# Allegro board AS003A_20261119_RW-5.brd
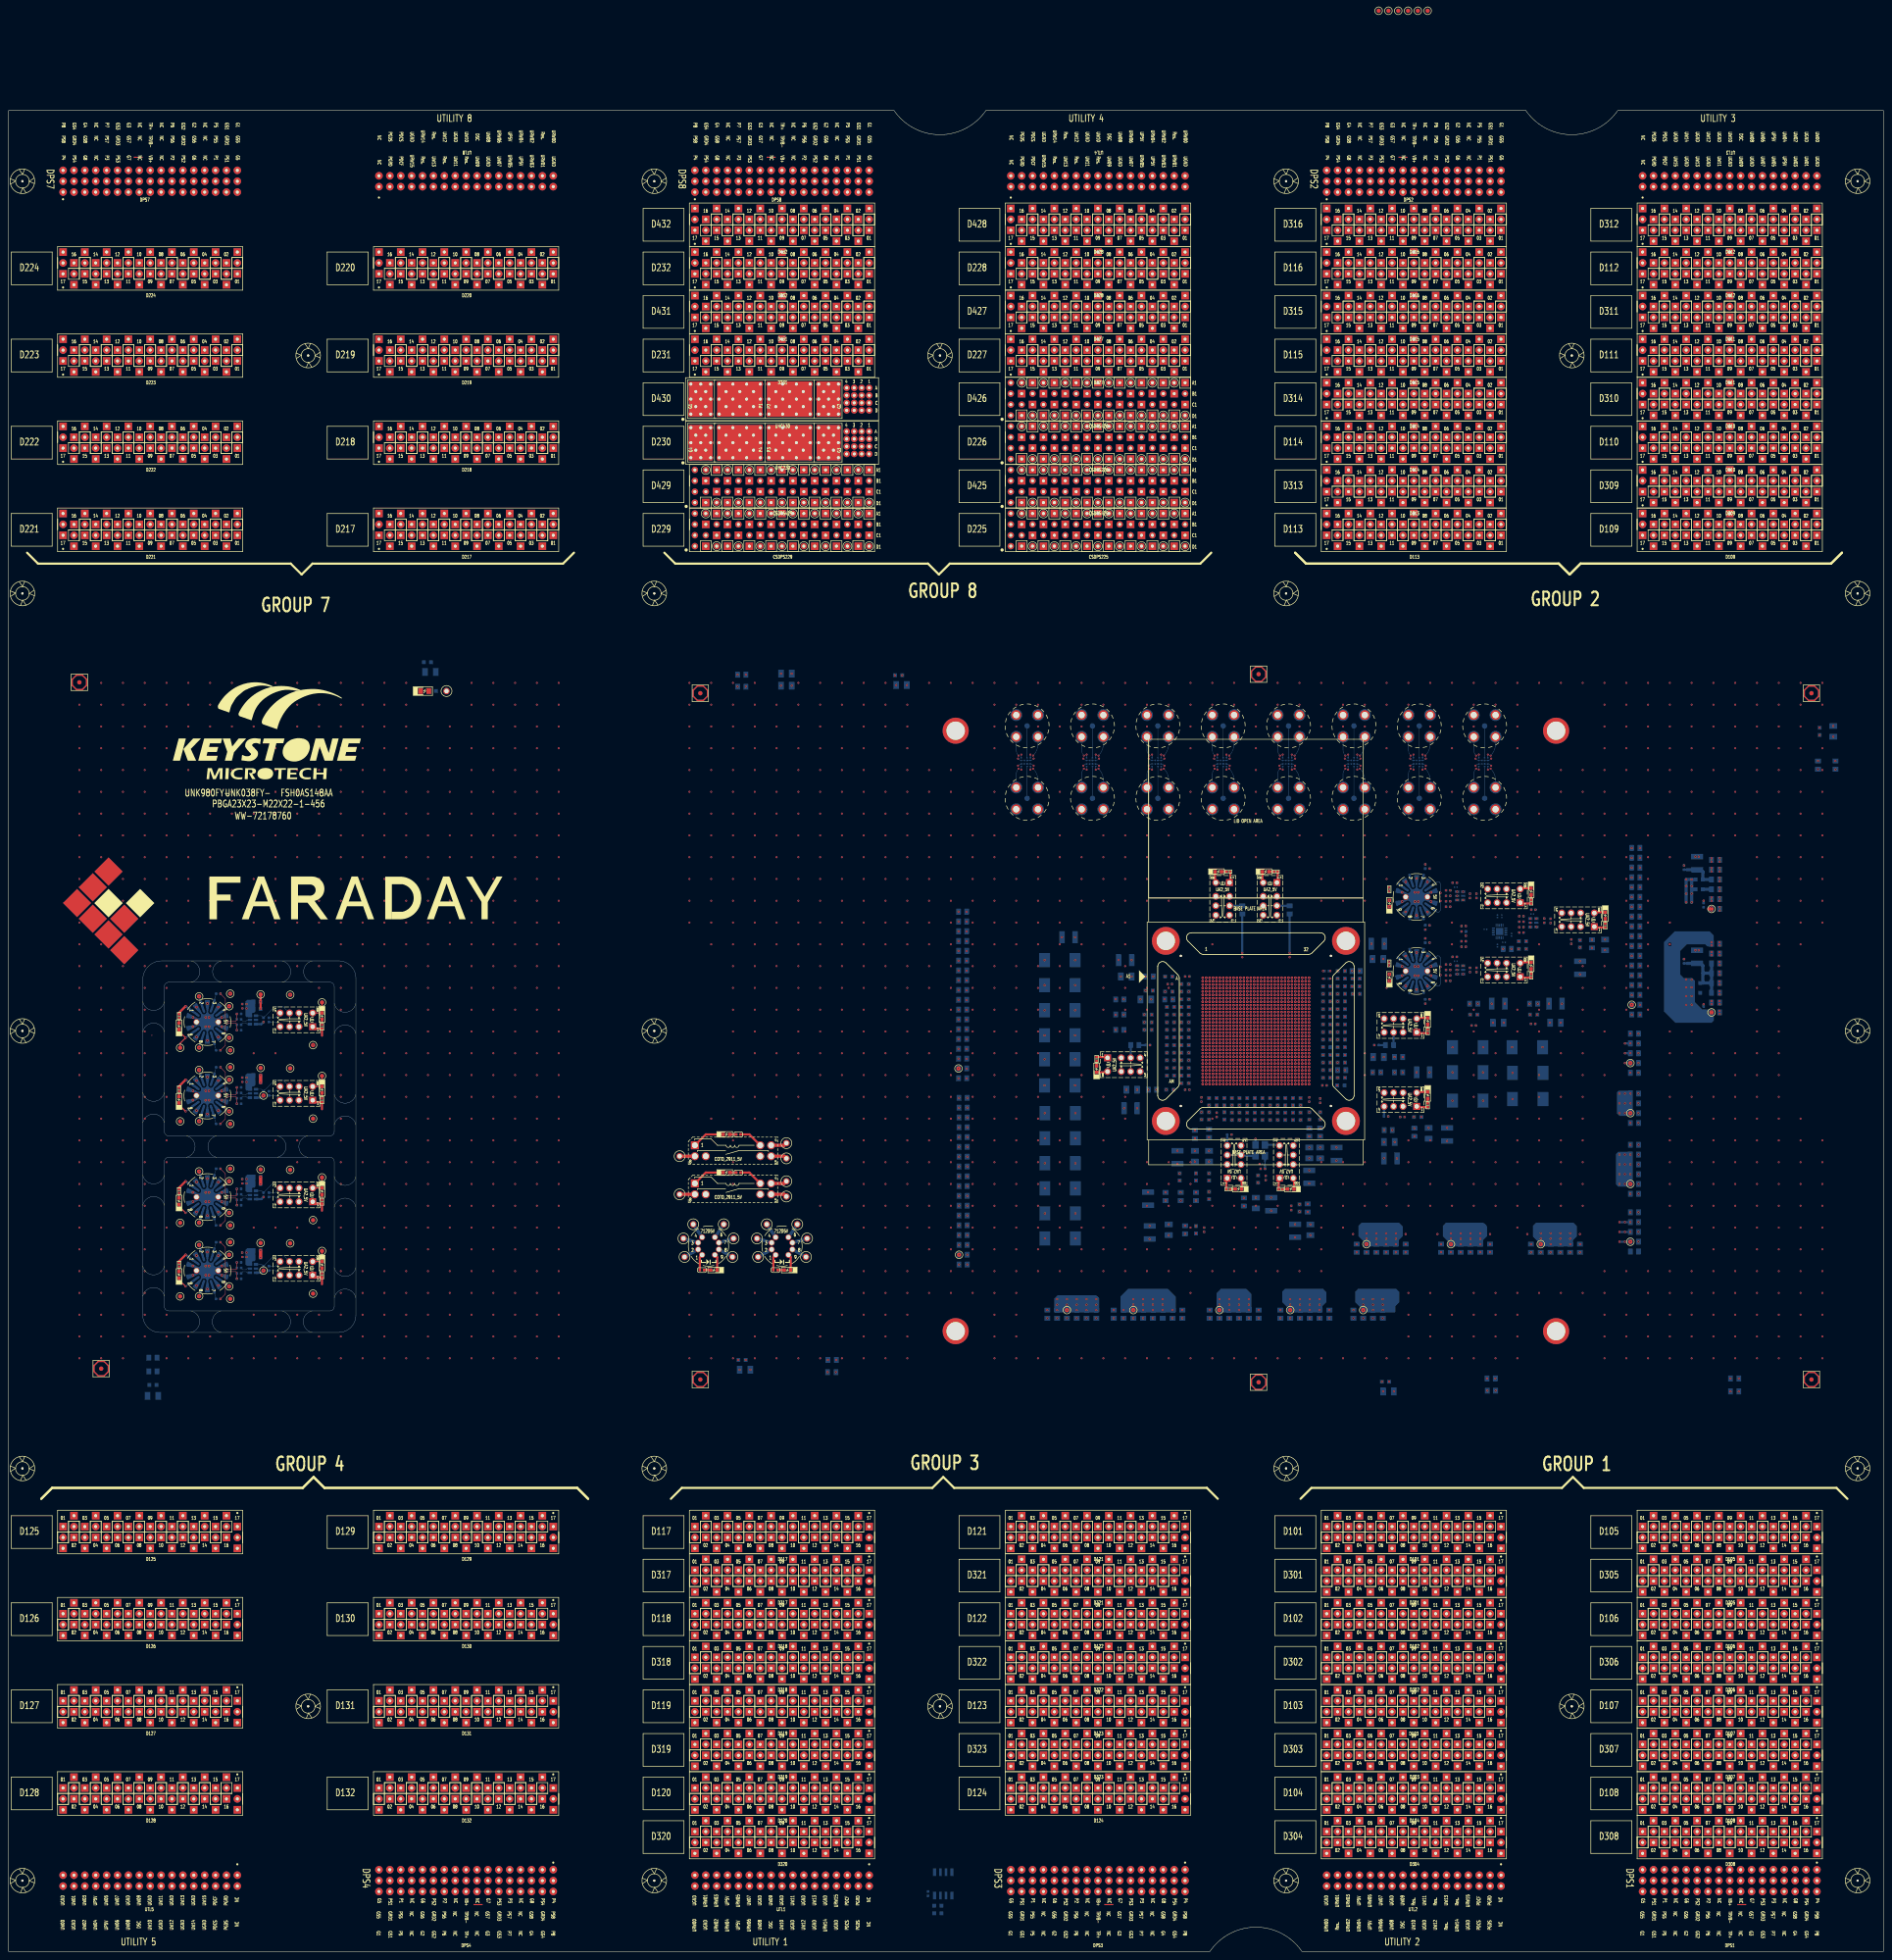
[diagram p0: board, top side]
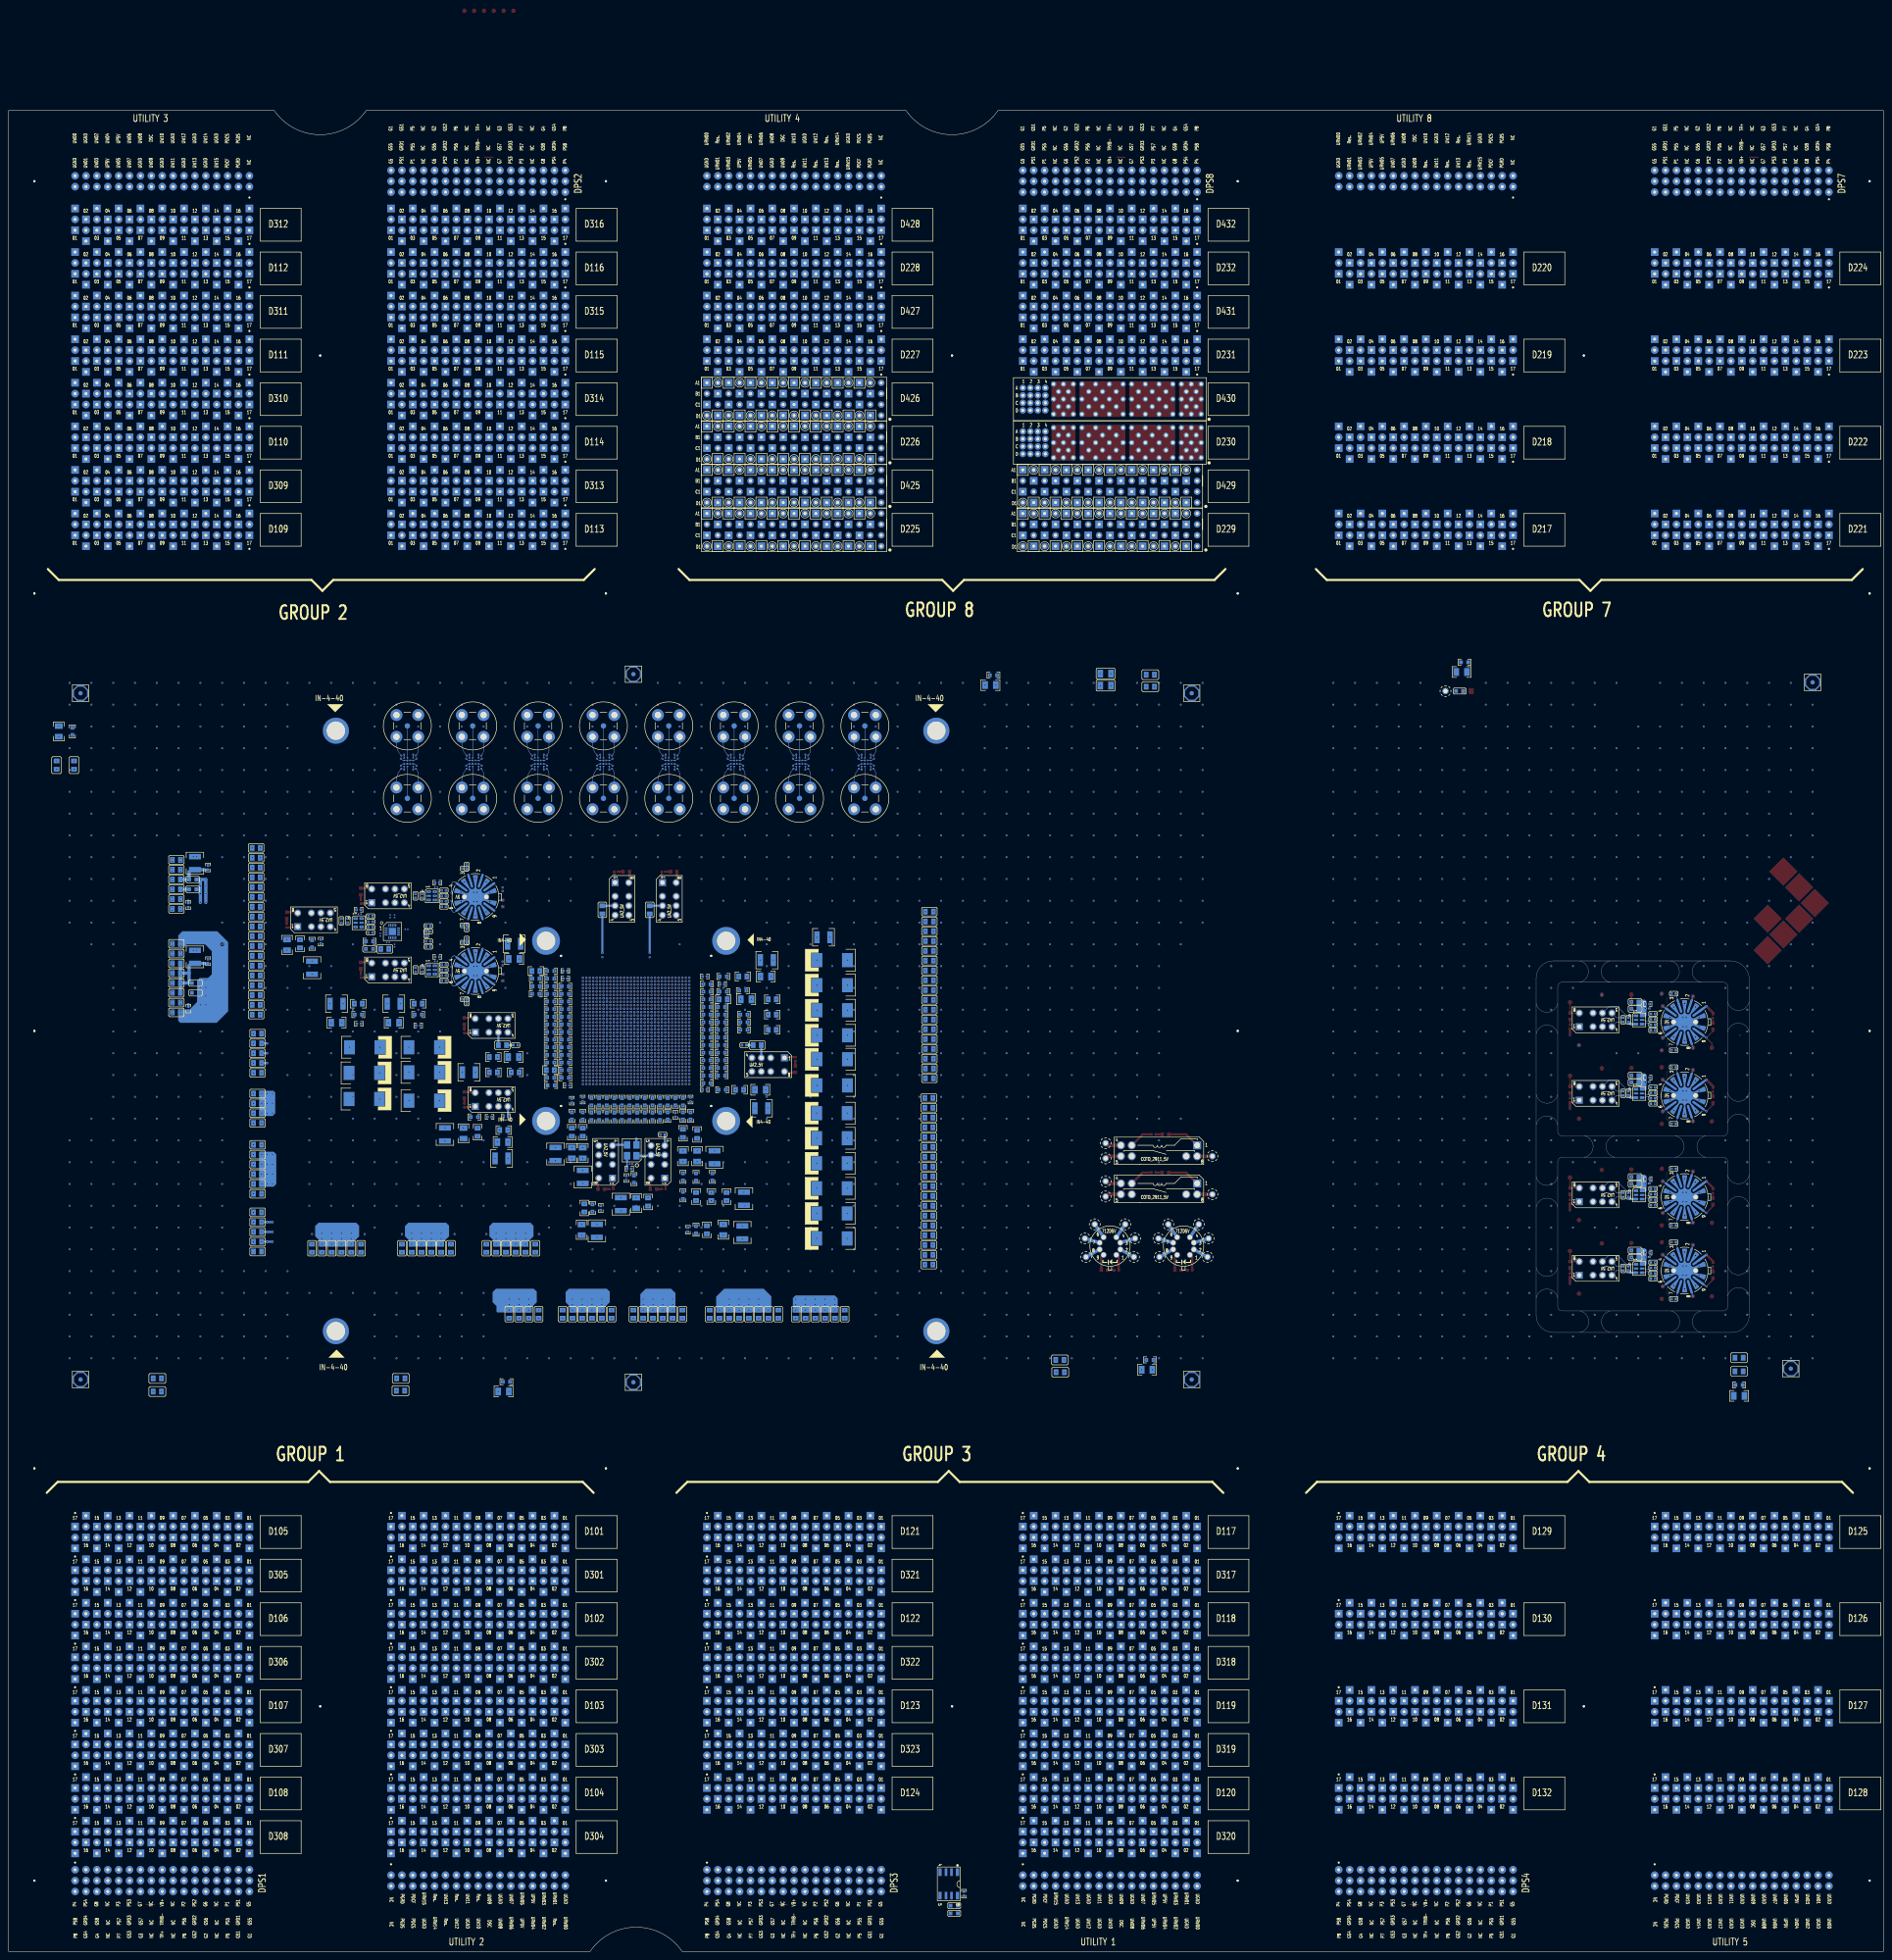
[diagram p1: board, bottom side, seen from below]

Outline 437.15 x 429.26 mm; copper layers: TOP, L02_DGND, L03_DIG, L04_DGND, L05_DIG, L06_DGND, L07_DIG, L08_DGND, L09_DIG, L10_DGND, L11_POWER, L12_POWER, L13_DGND, L14_POWER, L15_POWER, L16_DGND, L17_CBIT, L18_5V, L19_DGND, L20_POWER, L21_DGND, L22_POWER, L23_POWER, L24_DGND, L25_POWER, L26_POWER, L27_DGND, L28_POWER, L29_DGND, L30_DIG, L31_DGND, L32_DIG, L33_DGND, L34_DIG, L35_DGND, BOTTOM. Coordinates in mm from the lower left corner of the outline.
Outline path: 31.29,214.4 arc(33.81,216.46) 36.32,214.4 ; 31.29,193.19 arc(33.81,195.25) 36.32,193.19 ; 31.29,173.96 arc(33.81,176.01) 36.32,173.96 ; 31.29,152.75 arc(33.81,154.8) 36.32,152.75 ; 36.32,221.47 arc(33.81,219.42) 31.29,221.47 ; 36.32,200.26 arc(33.81,198.21) 31.29,200.26 ; 36.32,181.02 arc(33.81,178.97) 31.29,181.02 ; 36.32,159.81 arc(33.81,157.76) 31.29,159.81 ; 41.45,190.16 arc(43.49,187.66) 41.45,185.17 ; 42.49,149.35 arc(44.55,146.84) 42.49,144.32 ; 42.54,230.96 arc(44.58,228.47) 42.54,225.98 ; 48.51,185.17 arc(46.47,187.66) 48.51,190.16 ; 49.56,144.32 arc(47.5,146.84) 49.56,149.35 ; 49.61,225.98 arc(47.58,228.47) 49.61,230.96 ; 62.66,190.16 arc(64.7,187.66) 62.66,185.17 ; 63.7,149.35 arc(65.75,146.84) 63.7,144.32 ; 63.75,230.96 arc(65.79,228.47) 63.75,225.98 ; 69.72,185.17 arc(67.68,187.66) 69.72,190.16 ; 70.77,144.32 arc(68.71,146.84) 70.77,149.35 ; 70.82,225.98 arc(68.78,228.47) 70.82,230.96 ; 75.95,213.97 arc(78.46,216.02) 80.98,213.97 ; 75.95,192.76 arc(78.46,194.81) 80.98,192.76 ; 75.95,173.59 arc(78.46,175.64) 80.98,173.59 ; 75.95,152.38 arc(78.46,154.44) 80.98,152.38 ; 80.98,221.03 arc(78.46,218.98) 75.95,221.03 ; 80.98,199.82 arc(78.46,197.77) 75.95,199.82 ; 80.98,180.66 arc(78.46,178.6) 75.95,180.66 ; 80.98,159.45 arc(78.46,157.4) 75.95,159.45 ; 31.29,226.57 arc(32.58,229.68) 35.69,230.96 76.96,230.96 arc(79.8,229.79) 80.98,226.95 80.98,148.34 arc(79.8,145.5) 76.96,144.32 35.31,144.32 arc(32.47,145.5) 31.29,148.34 31.29,226.57 ; 36.32,224.96 36.32,191.18 arc(36.62,190.46) 37.34,190.16 74.93,190.16 arc(75.65,190.46) 75.95,191.18 75.95,224.96 arc(75.65,225.68) 74.93,225.98 37.34,225.98 arc(36.62,225.68) 36.32,224.96 ; 36.32,184.15 36.32,150.37 arc(36.62,149.65) 37.34,149.35 74.93,149.35 arc(75.65,149.65) 75.95,150.37 75.95,184.15 arc(75.65,184.87) 74.93,185.17 37.34,185.17 arc(36.62,184.87) 36.32,184.15

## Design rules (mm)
net group S1_OSC4_: nets S1_OSC4_N S1_OSC4_P
net group S1_OSC4_R_: nets S1_OSC4_R_N S1_OSC4_R_P
net group S1_OSC5_: nets S1_OSC5_N S1_OSC5_P
net group S1_OSC5_A_: nets S1_OSC5_A_N S1_OSC5_A_P
net group S1_OSC5_B_: nets S1_OSC5_B_N S1_OSC5_B_P
net group S1_OSC5_C_: nets S1_OSC5_C_N S1_OSC5_C_P
net group S1_OSC6_: nets S1_OSC6_N S1_OSC6_P
net group S1_OSC6_A_: nets S1_OSC6_A_N S1_OSC6_A_P
net group S1_OSC6_B_: nets S1_OSC6_B_N S1_OSC6_B_P
net group S1_OSC6_C_: nets S1_OSC6_C_N S1_OSC6_C_P
net group S1_OSC7_: nets S1_OSC7_N S1_OSC7_P
net group S1_OSC7_A_: nets S1_OSC7_A_N S1_OSC7_A_P
net group S1_OSC7_B_: nets S1_OSC7_B_N S1_OSC7_B_P
net group S1_OSC7_C_: nets S1_OSC7_C_N S1_OSC7_C_P
net group S1_OSC8_: nets S1_OSC8_N S1_OSC8_P
net group S1_OSC8_A_: nets S1_OSC8_A_N S1_OSC8_A_P
net group S1_OSC8_B_: nets S1_OSC8_B_N S1_OSC8_B_P
net group S1_OSC8_C_: nets S1_OSC8_C_N S1_OSC8_C_P
net group S1_PHY0_SYS_CLK1_: nets S1_PHY0_SYS_CLK1_N S1_PHY0_SYS_CLK1_P
net group S1_PHY0_SYS_CLK1R_: nets S1_PHY0_SYS_CLK1R_N S1_PHY0_SYS_CLK1R_P
net group S1_PHY0_SYS_CLK2_: nets S1_PHY0_SYS_CLK2_N S1_PHY0_SYS_CLK2_P
net group S1_PHY0_SYS_CLK3_: nets S1_PHY0_SYS_CLK3_N S1_PHY0_SYS_CLK3_P
net group S1_PHY0_SYS_CLK_: nets S1_PHY0_SYS_CLK_N S1_PHY0_SYS_CLK_P
net group S1_PHY1_SYS_CLK1_: nets S1_PHY1_SYS_CLK1_N S1_PHY1_SYS_CLK1_P
net group S1_PHY1_SYS_CLK1R_: nets S1_PHY1_SYS_CLK1R_N S1_PHY1_SYS_CLK1R_P
net group S1_PHY1_SYS_CLK2_: nets S1_PHY1_SYS_CLK2_N S1_PHY1_SYS_CLK2_P
net group S1_PHY1_SYS_CLK3_: nets S1_PHY1_SYS_CLK3_N S1_PHY1_SYS_CLK3_P
net group S1_PHY1_SYS_CLK_: nets S1_PHY1_SYS_CLK_N S1_PHY1_SYS_CLK_P

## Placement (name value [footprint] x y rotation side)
BD1  BD120-3A-S8-MU  [FB0805]  33.65 138.43 180 bottom
BD2  BD120-3A-S8-MU  [FB0805]  170.94 297.69 180 bottom
BD3  BD120-3A-S8-MU  [FB0805]  170.94 294.89 180 bottom
BD4  BD120-3A-S8-MU  [FB0805]  402.46 133.6 180 bottom
BD5  BD120-3A-S8-MU  [FB0805]  402.46 130.56 180 bottom
BD6  BD120-3A-S8-MU  [FB0805]  192.02 137.92 180 bottom
BD7  BD120-3A-S8-MU  [FB0805]  191.94 135.07 180 bottom
BD8  BD120-3A-S8-MU  [FB0805]  345.69 133.6 180 bottom
BD9  BD120-3A-S8-MU  [FB0805]  345.76 130.75 180 bottom
BD10  BD120-3A-S8-MU  [FB0805]  33.65 135.25 180 bottom
BD11  BD120-3A-S8-MU  [FB0805]  425.96 276.61 90 bottom
BD12  BD120-3A-S8-MU  [FB0805]  421.89 276.61 90 bottom
BD13  BD100-3A-S6-TDK  [FB0603]  393.57 225.81 0 bottom
BD14  BD100-3A-S6-TDK  [FB0603]  393.57 223.52 0 bottom
BD15  BD100-3A-S6-TDK  [FB0603]  394.21 249.94 0 bottom
BD16  BD100-3A-S6-TDK  [FB0603]  394.21 247.65 0 bottom
BD18  BD120-2.5A-S6  [FB0603]  352.99 233.75 180 bottom
BD19  BD100-3A-S6-TDK  [FB0603]  57.91 221.41 180 bottom
BD20  BD100-3A-S6-TDK  [FB0603]  57.91 219.75 180 bottom
BD21  BD100-3A-S6-TDK  [FB0603]  57.91 204.26 180 bottom
BD22  BD100-3A-S6-TDK  [FB0603]  57.91 202.61 180 bottom
BD23  BD100-3A-S6-TDK  [FB0603]  57.91 161.8 180 bottom
BD24  BD100-3A-S6-TDK  [FB0603]  57.91 163.45 180 bottom
BD25  BD100-3A-S6-TDK  [FB0603]  57.91 178.94 180 bottom
BD26  BD100-3A-S6-TDK  [FB0603]  57.91 180.59 180 bottom
C1  0.1U-25-X5R-S2-MU-1  [C0201_UNBGA]  291.23 213.83 270 bottom
C2  0.1U-25-X7R-S4-MU  [C0402]  306.83 201.93 0 bottom
C3  1U-25-X7R-S6-YA  [C0603]  310.64 201.93 0 bottom
C4  4.7U-25-X7R-S8-TY  [C0805]  321.69 191.52 0 bottom
C5  10U-25-X7R-SA  [C1206]  321.94 188.72 0 bottom
C6  22U-25-X7R-SB-MU  [C1210]  322.2 184.91 0 bottom
C7  0.1U-25-X5R-S2-MU-1  [C0201_UNBGA]  288.03 207.43 270 bottom
C8  0.1U-25-X5R-S2-MU-1  [C0201_UNBGA]  291.23 207.43 270 bottom
C9  0.1U-25-X5R-S2-MU-1  [C0201_UNBGA]  289.63 207.43 270 bottom
C10  0.1U-25-X7R-S4-MU  [C0402]  274.83 200.91 0 bottom
C11  1U-25-X7R-S6-YA  [C0603]  270.76 200.91 180 bottom
C12  4.7U-25-X7R-S8-TY  [C0805]  266.7 200.91 180 bottom
C13  10U-25-X7R-SA  [C1206]  261.87 200.91 180 bottom
C14  22U-25-X7R-SB-MU  [C1210]  261.62 196.6 180 bottom
C15  0.1U-25-X5R-S2-MU-1  [C0201_UNBGA]  298.43 222.63 270 bottom
C16  0.1U-25-X5R-S2-MU-1  [C0201_UNBGA]  298.43 221.03 270 bottom
C17  0.1U-25-X5R-S2-MU-1  [C0201_UNBGA]  298.43 219.43 270 bottom
C18  0.1U-25-X5R-S2-MU-1  [C0201_UNBGA]  298.43 217.83 270 bottom
C19  0.1U-25-X5R-S2-MU-1  [C0201_UNBGA]  298.43 216.23 270 bottom
C20  0.1U-25-X5R-S2-MU-1  [C0201_UNBGA]  298.43 214.63 270 bottom
C21  0.1U-25-X5R-S2-MU-1  [C0201_UNBGA]  298.43 213.03 270 bottom
C22  0.1U-25-X5R-S2-MU-1  [C0201_UNBGA]  298.43 211.43 270 bottom
C23  0.1U-25-X5R-S2-MU-1  [C0201_UNBGA]  298.43 209.83 270 bottom
C24  0.1U-25-X5R-S2-MU-1  [C0201_UNBGA]  298.43 208.23 270 bottom
C25  0.1U-25-X5R-S2-MU-1  [C0201_UNBGA]  298.43 206.63 270 bottom
C26  0.1U-25-X5R-S2-MU-1  [C0201_UNBGA]  292.83 218.63 270 bottom
C27  0.1U-25-X5R-S2-MU-1  [C0201_UNBGA]  288.03 218.63 270 bottom
C28  0.1U-25-X5R-S2-MU-1  [C0201_UNBGA]  295.23 217.83 270 bottom
C29  0.1U-25-X5R-S2-MU-1  [C0201_UNBGA]  293.63 217.83 270 bottom
C30  0.1U-25-X5R-S2-MU-1  [C0201_UNBGA]  290.43 217.83 270 bottom
C31  0.1U-25-X5R-S2-MU-1  [C0201_UNBGA]  291.23 218.63 270 bottom
C32  0.1U-25-X5R-S2-MU-1  [C0201_UNBGA]  287.23 217.83 270 bottom
C33  0.1U-25-X5R-S2-MU-1  [C0201_UNBGA]  289.63 217.03 270 bottom
C34  0.1U-25-X5R-S2-MU-1  [C0201_UNBGA]  288.83 217.83 270 bottom
C35  0.1U-25-X5R-S2-MU-1  [C0201_UNBGA]  292.03 217.83 270 bottom
C36  0.1U-25-X5R-S2-MU-1  [C0201_UNBGA]  291.23 217.03 270 bottom
C37  0.1U-25-X5R-S2-MU-1  [C0201_UNBGA]  289.63 218.63 270 bottom
C38  0.1U-25-X5R-S2-MU-1  [C0201_UNBGA]  286.43 218.63 270 bottom
C39  0.1U-25-X5R-S2-MU-1  [C0201_UNBGA]  286.43 220.23 270 bottom
C40  0.1U-25-X5R-S2-MU-1  [C0201_UNBGA]  292.03 219.43 270 bottom
C41  0.1U-25-X5R-S2-MU-1  [C0201_UNBGA]  290.43 219.43 270 bottom
C42  0.1U-25-X5R-S2-MU-1  [C0201_UNBGA]  288.83 219.43 270 bottom
C43  0.1U-25-X5R-S2-MU-1  [C0201_UNBGA]  287.23 219.43 270 bottom
C44  0.1U-25-X5R-S2-MU-1  [C0201_UNBGA]  295.23 219.43 270 bottom
C45  0.1U-25-X5R-S2-MU-1  [C0201_UNBGA]  294.43 220.23 270 bottom
C46  0.1U-25-X5R-S2-MU-1  [C0201_UNBGA]  294.43 218.63 270 bottom
C47  0.1U-25-X5R-S2-MU-1  [C0201_UNBGA]  293.63 219.43 270 bottom
C48  0.1U-25-X5R-S2-MU-1  [C0201_UNBGA]  283.23 221.83 270 bottom
C49  0.1U-25-X5R-S2-MU-1  [C0201_UNBGA]  283.23 213.83 270 bottom
C50  0.1U-25-X5R-S2-MU-1  [C0201_UNBGA]  283.23 215.43 270 bottom
C51  0.1U-25-X5R-S2-MU-1  [C0201_UNBGA]  283.23 217.03 270 bottom
C52  0.1U-25-X5R-S2-MU-1  [C0201_UNBGA]  283.23 218.63 270 bottom
C53  0.1U-25-X5R-S2-MU-1  [C0201_UNBGA]  283.23 220.23 270 bottom
C54  0.1U-25-X5R-S2-MU-1  [C0201_UNBGA]  283.23 207.43 270 bottom
C55  0.1U-25-X5R-S2-MU-1  [C0201_UNBGA]  283.23 209.03 270 bottom
C56  0.1U-25-X5R-S2-MU-1  [C0201_UNBGA]  283.23 210.63 270 bottom
C57  0.1U-25-X5R-S2-MU-1  [C0201_UNBGA]  283.23 212.23 270 bottom
C58  0.1U-25-X5R-S2-MU-1  [C0201_UNBGA]  288.03 215.43 270 bottom
C59  0.1U-25-X5R-S2-MU-1  [C0201_UNBGA]  287.23 216.23 270 bottom
C60  0.1U-25-X5R-S2-MU-1  [C0201_UNBGA]  286.43 217.03 270 bottom
C61  0.1U-25-X5R-S2-MU-1  [C0201_UNBGA]  287.23 211.43 270 bottom
C62  0.1U-25-X5R-S2-MU-1  [C0201_UNBGA]  286.43 212.23 270 bottom
C63  0.1U-25-X5R-S2-MU-1  [C0201_UNBGA]  287.23 213.03 270 bottom
C64  0.1U-25-X5R-S2-MU-1  [C0201_UNBGA]  286.43 213.83 270 bottom
C65  0.1U-25-X5R-S2-MU-1  [C0201_UNBGA]  286.43 215.43 270 bottom
C66  0.1U-25-X5R-S2-MU-1  [C0201_UNBGA]  287.23 208.23 270 bottom
C67  0.1U-25-X5R-S2-MU-1  [C0201_UNBGA]  286.43 209.03 270 bottom
C68  0.1U-25-X5R-S2-MU-1  [C0201_UNBGA]  287.23 209.83 270 bottom
C69  0.1U-25-X5R-S2-MU-1  [C0201_UNBGA]  286.43 210.63 270 bottom
C70  0.1U-25-X5R-S2-MU-1  [C0201_UNBGA]  295.23 211.43 270 bottom
C71  0.1U-25-X5R-S2-MU-1  [C0201_UNBGA]  295.23 213.03 270 bottom
C72  0.1U-25-X5R-S2-MU-1  [C0201_UNBGA]  295.23 216.23 270 bottom
C73  0.1U-25-X5R-S2-MU-1  [C0201_UNBGA]  295.23 209.83 270 bottom
C74  0.1U-25-X5R-S2-MU-1  [C0201_UNBGA]  295.23 208.23 270 bottom
C75  0.1U-25-X5R-S2-MU-1  [C0201_UNBGA]  294.43 209.03 270 bottom
C76  0.1U-25-X5R-S2-MU-1  [C0201_UNBGA]  294.43 215.43 270 bottom
C77  0.1U-25-X5R-S2-MU-1  [C0201_UNBGA]  294.43 213.83 270 bottom
C78  0.1U-25-X5R-S2-MU-1  [C0201_UNBGA]  294.43 212.23 270 bottom
C79  0.1U-25-X5R-S2-MU-1  [C0201_UNBGA]  294.43 210.63 270 bottom
C80  0.1U-25-X5R-S2-MU-1  [C0201_UNBGA]  294.43 217.03 270 bottom
C81  0.1U-25-X5R-S2-MU-1  [C0201_UNBGA]  287.23 214.63 270 bottom
C82  0.1U-25-X5R-S2-MU-1  [C0201_UNBGA]  295.23 214.63 270 bottom
C83  0.1U-25-X5R-S2-MU-1  [C0201_UNBGA]  292.83 207.43 270 bottom
C84  0.1U-25-X5R-S2-MU-1  [C0201_UNBGA]  290.43 213.03 270 bottom
C85  0.1U-25-X5R-S2-MU-1  [C0201_UNBGA]  284.83 210.63 270 bottom
C86  0.1U-25-X5R-S2-MU-1  [C0201_UNBGA]  285.63 211.43 270 bottom
C87  0.1U-25-X5R-S2-MU-1  [C0201_UNBGA]  284.03 211.43 270 bottom
C88  0.1U-25-X5R-S2-MU-1  [C0201_UNBGA]  284.03 208.23 270 bottom
C89  0.1U-25-X5R-S2-MU-1  [C0201_UNBGA]  284.83 218.63 270 bottom
C90  0.1U-25-X5R-S2-MU-1  [C0201_UNBGA]  284.83 209.03 270 bottom
C91  0.1U-25-X5R-S2-MU-1  [C0201_UNBGA]  285.63 208.23 270 bottom
C92  0.1U-25-X5R-S2-MU-1  [C0201_UNBGA]  284.03 219.43 270 bottom
C93  0.1U-25-X5R-S2-MU-1  [C0201_UNBGA]  284.83 215.43 270 bottom
C94  0.1U-25-X5R-S2-MU-1  [C0201_UNBGA]  284.03 216.23 270 bottom
C95  0.1U-25-X5R-S2-MU-1  [C0201_UNBGA]  284.03 217.83 270 bottom
C96  0.1U-25-X5R-S2-MU-1  [C0201_UNBGA]  284.03 221.03 270 bottom
C97  0.1U-25-X5R-S2-MU-1  [C0201_UNBGA]  284.83 220.23 270 bottom
C98  0.1U-25-X5R-S2-MU-1  [C0201_UNBGA]  284.83 213.83 270 bottom
C99  0.1U-25-X5R-S2-MU-1  [C0201_UNBGA]  284.83 221.83 270 bottom
C100  0.1U-25-X5R-S2-MU-1  [C0201_UNBGA]  284.03 209.83 270 bottom
C101  0.1U-25-X5R-S2-MU-1  [C0201_UNBGA]  285.63 209.83 270 bottom
C102  0.1U-25-X5R-S2-MU-1  [C0201_UNBGA]  285.63 216.23 270 bottom
C103  0.1U-25-X5R-S2-MU-1  [C0201_UNBGA]  286.03 207.03 0 bottom
C104  0.1U-25-X5R-S2-MU-1  [C0201_UNBGA]  284.83 207.43 270 bottom
C105  0.1U-25-X5R-S2-MU-1  [C0201_UNBGA]  284.83 217.03 270 bottom
C106  0.1U-25-X5R-S2-MU-1  [C0201_UNBGA]  284.83 212.23 270 bottom
C107  0.1U-25-X5R-S2-MU-1  [C0201_UNBGA]  284.03 213.03 270 bottom
C108  0.1U-25-X5R-S2-MU-1  [C0201_UNBGA]  285.63 213.03 270 bottom
C109  0.1U-25-X5R-S2-MU-1  [C0201_UNBGA]  284.03 214.63 270 bottom
C110  0.1U-25-X5R-S2-MU-1  [C0201_UNBGA]  285.63 214.63 270 bottom
C111  0.1U-25-X5R-S2-MU-1  [C0201_UNBGA]  296.03 212.23 270 bottom
C112  0.1U-25-X5R-S2-MU-1  [C0201_UNBGA]  296.03 213.83 270 bottom
C113  0.1U-25-X5R-S2-MU-1  [C0201_UNBGA]  296.03 209.03 270 bottom
C114  0.1U-25-X5R-S2-MU-1  [C0201_UNBGA]  296.03 210.63 270 bottom
C115  0.1U-25-X5R-S2-MU-1  [C0201_UNBGA]  296.83 209.83 270 bottom
C116  0.1U-25-X5R-S2-MU-1  [C0201_UNBGA]  296.43 207.03 180 bottom
C117  0.1U-25-X5R-S2-MU-1  [C0201_UNBGA]  296.83 208.23 270 bottom
C118  0.1U-25-X5R-S2-MU-1  [C0201_UNBGA]  296.83 211.43 270 bottom
C119  0.1U-25-X5R-S2-MU-1  [C0201_UNBGA]  296.83 213.03 270 bottom
C120  0.1U-25-X5R-S2-MU-1  [C0201_UNBGA]  296.03 215.43 270 bottom
C121  0.1U-25-X5R-S2-MU-1  [C0201_UNBGA]  296.83 214.63 270 bottom
C122  0.1U-25-X5R-S2-MU-1  [C0201_UNBGA]  296.83 216.23 270 bottom
C123  0.1U-25-X5R-S2-MU-1  [C0201_UNBGA]  296.03 217.03 270 bottom
C124  0.1U-25-X5R-S2-MU-1  [C0201_UNBGA]  297.63 207.43 270 bottom
C125  0.1U-25-X5R-S2-MU-1  [C0201_UNBGA]  297.63 209.03 270 bottom
C126  0.1U-25-X5R-S2-MU-1  [C0201_UNBGA]  296.83 217.83 270 bottom
C127  0.1U-25-X5R-S2-MU-1  [C0201_UNBGA]  296.83 219.43 270 bottom
C128  0.1U-25-X5R-S2-MU-1  [C0201_UNBGA]  297.63 210.63 270 bottom
C129  0.1U-25-X5R-S2-MU-1  [C0201_UNBGA]  297.63 220.23 270 bottom
C130  0.1U-25-X5R-S2-MU-1  [C0201_UNBGA]  297.63 221.83 270 bottom
C131  0.1U-25-X5R-S2-MU-1  [C0201_UNBGA]  297.63 212.23 270 bottom
C132  0.1U-25-X5R-S2-MU-1  [C0201_UNBGA]  297.63 215.43 270 bottom
C133  0.1U-25-X5R-S2-MU-1  [C0201_UNBGA]  297.63 213.83 270 bottom
C134  0.1U-25-X5R-S2-MU-1  [C0201_UNBGA]  297.63 217.03 270 bottom
C135  0.1U-25-X5R-S2-MU-1  [C0201_UNBGA]  296.83 221.03 270 bottom
C136  0.1U-25-X5R-S2-MU-1  [C0201_UNBGA]  297.63 218.63 270 bottom
C137  0.1U-25-X7R-S4-MU  [C0402]  321.2 194.71 0 bottom
C138  0.1U-25-X5R-S2-MU-1  [C0201_UNBGA]  290.43 214.63 270 bottom
C139  0.1U-25-X5R-S2-MU-1  [C0201_UNBGA]  290.43 211.43 270 bottom
C140  0.1U-25-X5R-S2-MU-1  [C0201_UNBGA]  288.83 216.23 270 bottom
C141  0.1U-25-X5R-S2-MU-1  [C0201_UNBGA]  290.43 208.23 270 bottom
C142  0.1U-25-X5R-S2-MU-1  [C0201_UNBGA]  290.43 209.83 270 bottom
C143  0.1U-25-X5R-S2-MU-1  [C0201_UNBGA]  288.83 209.83 270 bottom
C144  0.1U-25-X5R-S2-MU-1  [C0201_UNBGA]  288.03 209.03 270 bottom
C145  0.1U-25-X5R-S2-MU-1  [C0201_UNBGA]  291.23 212.23 270 bottom
C146  0.1U-25-X5R-S2-MU-1  [C0201_UNBGA]  288.83 208.23 270 bottom
C147  0.1U-25-X5R-S2-MU-1  [C0201_UNBGA]  289.63 209.03 270 bottom
C148  0.1U-25-X5R-S2-MU-1  [C0201_UNBGA]  289.63 212.23 270 bottom
C149  0.1U-25-X5R-S2-MU-1  [C0201_UNBGA]  288.83 211.43 270 bottom
C150  0.1U-25-X5R-S2-MU-1  [C0201_UNBGA]  288.03 210.63 270 bottom
C151  0.1U-25-X5R-S2-MU-1  [C0201_UNBGA]  289.63 210.63 270 bottom
C152  0.1U-25-X5R-S2-MU-1  [C0201_UNBGA]  288.03 213.83 270 bottom
C153  0.1U-25-X5R-S2-MU-1  [C0201_UNBGA]  288.83 213.03 270 bottom
C154  0.1U-25-X5R-S2-MU-1  [C0201_UNBGA]  289.63 213.83 270 bottom
C155  0.1U-25-X5R-S2-MU-1  [C0201_UNBGA]  288.03 212.23 270 bottom
C156  0.1U-25-X5R-S2-MU-1  [C0201_UNBGA]  291.23 215.43 270 bottom
C157  0.1U-25-X5R-S2-MU-1  [C0201_UNBGA]  293.63 209.83 270 bottom
C158  0.1U-25-X5R-S2-MU-1  [C0201_UNBGA]  293.63 211.43 270 bottom
C159  0.1U-25-X5R-S2-MU-1  [C0201_UNBGA]  289.63 215.43 270 bottom
C160  0.1U-25-X5R-S2-MU-1  [C0201_UNBGA]  288.83 214.63 270 bottom
C161  0.1U-25-X5R-S2-MU-1  [C0201_UNBGA]  292.83 210.63 270 bottom
C162  0.1U-25-X5R-S2-MU-1  [C0201_UNBGA]  292.83 209.03 270 bottom
C163  0.1U-25-X5R-S2-MU-1  [C0201_UNBGA]  293.63 216.23 270 bottom
C164  0.1U-25-X5R-S2-MU-1  [C0201_UNBGA]  293.63 208.23 270 bottom
C165  0.1U-25-X5R-S2-MU-1  [C0201_UNBGA]  292.03 216.23 270 bottom
C166  0.1U-25-X5R-S2-MU-1  [C0201_UNBGA]  292.83 217.03 270 bottom
C167  0.1U-25-X5R-S2-MU-1  [C0201_UNBGA]  292.83 215.43 270 bottom
C168  0.1U-25-X5R-S2-MU-1  [C0201_UNBGA]  292.83 213.83 270 bottom
C169  0.1U-25-X5R-S2-MU-1  [C0201_UNBGA]  292.83 212.23 270 bottom
C170  0.1U-25-X5R-S2-MU-1  [C0201_UNBGA]  292.03 213.03 270 bottom
C171  0.1U-25-X5R-S2-MU-1  [C0201_UNBGA]  292.03 211.43 270 bottom
C172  0.1U-25-X5R-S2-MU-1  [C0201_UNBGA]  292.03 214.63 270 bottom
C173  0.1U-25-X5R-S2-MU-1  [C0201_UNBGA]  293.63 214.63 270 bottom
C174  0.1U-25-X5R-S2-MU-1  [C0201_UNBGA]  291.23 210.63 270 bottom
C175  0.1U-25-X5R-S2-MU-1  [C0201_UNBGA]  291.23 209.03 270 bottom
C176  0.1U-25-X5R-S2-MU-1  [C0201_UNBGA]  292.03 208.23 270 bottom
C177  0.1U-25-X5R-S2-MU-1  [C0201_UNBGA]  293.63 213.03 270 bottom
C178  0.1U-25-X5R-S2-MU-1  [C0201_UNBGA]  292.03 209.83 270 bottom
C179  0.1U-25-X5R-S2-MU-1  [C0201_UNBGA]  288.03 217.03 270 bottom
C180  0.1U-25-X5R-S2-MU-1  [C0201_UNBGA]  290.43 216.23 270 bottom
C181  0.1U-25-X7R-S4-MU  [C0402]  355.47 216.28 180 bottom
C182  1U-25-X7R-S6-YA  [C0603]  355.6 218.44 180 bottom
C183  4.7U-25-X7R-S8-TY  [C0805]  355.6 220.98 180 bottom
C184  10U-25-X7R-SA  [C1206]  360.68 216.53 0 bottom
C185  22U-25-X7R-SB-MU  [C1210]  360.68 220.98 0 bottom
C186  1U-25-X7R-S6-YA  [C0603]  341.63 218.44 180 bottom
C187  0.1U-25-X7R-S4-MU  [C0402]  341.63 215.9 180 bottom
C188  10U-25-X7R-SA  [C1206]  347.34 216.53 0 bottom
C189  4.7U-25-X7R-S8-TY  [C0805]  341.63 220.98 180 bottom
C190  22U-25-X7R-SB-MU  [C1210]  347.34 220.98 0 bottom
C191  1U-25-X7R-S6-YA  [C0603]  270.51 227.33 180 bottom
C192  0.1U-25-X7R-S4-MU  [C0402]  274.83 227.33 180 bottom
C193  10U-25-X7R-SA  [C1206]  260.6 227.33 180 bottom
C194  4.7U-25-X7R-S8-TY  [C0805]  265.94 227.33 180 bottom
C195  22U-25-X7R-SB-MU  [C1210]  260.35 231.14 180 bottom
C196  1U-25-X7R-S6-YA  [C0603]  310.74 228.6 0 bottom
C197  10U-25-X7R-SA  [C1206]  319.28 231.39 0 bottom
C198  0.1U-25-X7R-S4-MU  [C0402]  307.34 228.6 0 bottom
C199  4.7U-25-X7R-S8-TY  [C0805]  314.2 228.6 0 bottom
C200  22U-25-X7R-SB-MU  [C1210]  319.28 234.95 0 bottom
C201  1U-25-X7R-S6-YA  [C0603]  276.86 168.28 270 bottom
C202  0.1U-25-X7R-S4-MU  [C0402]  278.76 168.28 270 bottom
C203  10U-25-X7R-SA  [C1206]  270.51 168.28 270 bottom
C204  4.7U-25-X7R-S8-TY  [C0805]  274.32 168.28 270 bottom
C205  22U-25-X7R-SB-MU  [C1210]  266.06 167.64 270 bottom
C206  1U-25-X7R-S6-YA  [C0603]  305.82 194.82 270 bottom
C207  0.1U-25-X7R-S4-MU  [C0402]  305.82 198.37 270 bottom
C208  10U-25-X7R-SA  [C1206]  305.82 186.18 270 bottom
C209  4.7U-25-X7R-S8-TY  [C0805]  305.82 191.01 270 bottom
C210  22U-25-X7R-SB-MU  [C1210]  309.63 185.93 270 bottom
C211  1U-25-X7R-S6-YA  [C0603]  328.55 194.56 0 bottom
C212  0.1U-25-X7R-S4-MU  [C0402]  324.99 194.56 0 bottom
C213  10U-25-X7R-SA  [C1206]  331.09 190.75 270 bottom
C214  4.7U-25-X7R-S8-TY  [C0805]  327.79 191.01 270 bottom
C215  22U-25-X7R-SB-MU  [C1210]  335.41 190.5 270 bottom
C216  1U-25-X7R-S6-YA  [C0603]  300.99 173.35 270 bottom
C217  10U-25-X7R-SA  [C1206]  303.53 168.25 270 bottom
C218  0.1U-25-X7R-S4-MU  [C0402]  299.08 173.35 270 bottom
C219  4.7U-25-X7R-S8-TY  [C0805]  302.89 173.35 270 bottom
C220  22U-25-X7R-SB-MU  [C1210]  299.97 168.02 270 bottom
C221  10U-25-X7R-SA  [C1206]  303.28 186.18 270 bottom
C222  1U-25-X7R-S6-YA  [C0603]  303.28 194.82 270 bottom
C223  0.1U-25-X7R-S4-MU  [C0402]  303.28 198.63 270 bottom
C224  4.7U-25-X7R-S8-TY  [C0805]  303.28 191.01 270 bottom
C225  22U-25-X7R-SB-MU  [C1210]  303.28 180.59 270 bottom
C226  0.1U-25-X7R-S4-MU  [C0402]  278.13 198.63 270 bottom
C227  1U-25-X7R-S6-YA  [C0603]  278.13 194.82 270 bottom
C228  4.7U-25-X7R-S8-TY  [C0805]  276.61 190.5 270 bottom
C229  10U-25-X7R-SA  [C1206]  276.61 185.42 270 bottom
C230  22U-25-X7R-SB-MU  [C1210]  272.54 185.17 270 bottom
C249  0.1U-25-X7R-S4-MU  [C0402]  337.19 231.9 180 bottom
C250  0.1U-25-X7R-S4-MU  [C0402]  337.19 249.17 180 bottom
C251  0.1U-25-X7R-S4-MU  [C0402]  292.45 182.48 180 bottom
C252  0.22U-16-X7R-S2-PPI  [C0201]  343.87 276.91 0 bottom
C253  0.22U-16-X7R-S2-PPI  [C0201]  343.87 277.7 0 bottom
C254  NC/0.1U-16-X7R-S2-PPI  [C0201]  344.17 276.61 90 bottom
C255  NC/0.1U-16-X7R-S2-PPI  [C0201]  344.17 278 270 bottom
C256  0.22U-16-X7R-S2-PPI  [C0201]  328.63 276.91 0 bottom
C257  0.22U-16-X7R-S2-PPI  [C0201]  328.63 277.7 0 bottom
C258  NC/0.1U-16-X7R-S2-PPI  [C0201]  328.93 276.61 90 bottom
C259  NC/0.1U-16-X7R-S2-PPI  [C0201]  328.93 278 270 bottom
C260  0.22U-16-X7R-S2-PPI  [C0201]  313.39 276.91 0 bottom
C261  0.22U-16-X7R-S2-PPI  [C0201]  313.39 277.7 0 bottom
C262  NC/0.1U-16-X7R-S2-PPI  [C0201]  313.69 278 270 bottom
C263  NC/0.1U-16-X7R-S2-PPI  [C0201]  313.69 276.61 90 bottom
C264  0.22U-16-X7R-S2-PPI  [C0201]  298.15 276.91 0 bottom
C265  0.22U-16-X7R-S2-PPI  [C0201]  298.15 277.7 0 bottom
C266  NC/0.1U-16-X7R-S2-PPI  [C0201]  298.45 278 270 bottom
C267  NC/0.1U-16-X7R-S2-PPI  [C0201]  298.45 276.61 90 bottom
C268  0.22U-16-X7R-S2-PPI  [C0201]  282.91 276.91 0 bottom
C269  0.22U-16-X7R-S2-PPI  [C0201]  282.91 277.7 0 bottom
C270  NC/0.1U-16-X7R-S2-PPI  [C0201]  283.21 278 270 bottom
C271  NC/0.1U-16-X7R-S2-PPI  [C0201]  283.21 276.61 90 bottom
C272  0.22U-16-X7R-S2-PPI  [C0201]  267.67 276.91 0 bottom
C273  0.22U-16-X7R-S2-PPI  [C0201]  267.67 277.7 0 bottom
C274  NC/0.1U-16-X7R-S2-PPI  [C0201]  267.97 278 270 bottom
C275  NC/0.1U-16-X7R-S2-PPI  [C0201]  267.97 276.61 90 bottom
C276  0.22U-16-X7R-S2-PPI  [C0201]  252.43 276.91 0 bottom
C277  0.22U-16-X7R-S2-PPI  [C0201]  252.43 277.7 0 bottom
C278  NC/0.1U-16-X7R-S2-PPI  [C0201]  252.73 278 270 bottom
C279  NC/0.1U-16-X7R-S2-PPI  [C0201]  252.73 276.61 90 bottom
C280  0.22U-16-X7R-S2-PPI  [C0201]  237.19 276.91 0 bottom
C281  0.22U-16-X7R-S2-PPI  [C0201]  237.19 277.7 0 bottom
C282  NC/0.1U-16-X7R-S2-PPI  [C0201]  237.49 278 270 bottom
C283  NC/0.1U-16-X7R-S2-PPI  [C0201]  237.49 276.61 90 bottom
C285  47U-10-X7R-SB-MU  [C1210]  393.7 231.9 90 bottom
C286  0.1U-25-X7R-S4-MU  [C0402]  395.22 219.84 90 bottom
C287  0.1U-25-X7R-S4-MU  [C0402]  390.65 230.89 90 bottom
C288  47U-10-X7R-SB-MU  [C1210]  393.7 253.75 90 bottom
C289  0.1U-25-X7R-S4-MU  [C0402]  395.22 243.97 90 bottom
C290  0.1U-25-X7R-S4-MU  [C0402]  390.65 252.73 90 bottom
C291  1U-25-X7R-S6-YA  [C0603]  366.39 234.95 270 bottom
C292  0.1U-25-X7R-S4-MU  [C0402]  364.36 235.46 270 bottom
C293  4.7U-25-X7R-S8-TY  [C0805]  369.19 234.95 270 bottom
C294  10U-25-X7R-SA  [C1206]  372.24 234.7 270 bottom
C295  22U-25-X7R-SB-MU  [C1210]  366.39 229.36 270 bottom
C296  1U-25-X7R-S6-YA  [C0603]  291.34 180.09 270 bottom
C297  0.1U-25-X7R-S4-MU  [C0402]  293.12 180.34 270 bottom
C298  4.7U-25-X7R-S8-TY  [C0805]  288.04 174.75 270 bottom
C299  10U-25-X7R-SA  [C1206]  290.83 174.5 270 bottom
C300  22U-25-X7R-SB-MU  [C1210]  294.39 174.24 270 bottom
C332  0.47U-25-X5R-S6-SS  [C0603]  270.92 214.88 180 bottom
C333  0.47U-25-X5R-S6-SS  [C0603]  270.92 218.44 180 bottom
C334  0.47U-25-X5R-S6-SS  [C0603]  270.92 216.66 180 bottom
C335  0.47U-25-X5R-S6-SS  [C0603]  270.92 207.77 180 bottom
C336  0.47U-25-X5R-S6-SS  [C0603]  270.92 220.22 180 bottom
C337  0.47U-25-X5R-S6-SS  [C0603]  270.92 211.33 180 bottom
C338  0.47U-25-X5R-S6-SS  [C0603]  270.92 209.55 180 bottom
C339  0.47U-25-X5R-S6-SS  [C0603]  270.92 213.11 180 bottom
C340  10U-25-X-S6-MU  [C0603]  265.68 218.44 180 bottom
C341  10U-25-X-S6-MU  [C0603]  265.68 216.66 180 bottom
C342  10U-25-X-S6-MU  [C0603]  265.68 214.88 180 bottom
C343  470U-4-T-SD-LOESR  [CODE_D]  245.11 231.14 180 bottom
C344  470U-4-T-SD-LOESR  [CODE_D]  245.11 225.3 180 bottom
C345  470U-4-T-SD-LOESR  [CODE_D]  245.11 219.46 180 bottom
C346  0.22U-25-X8R-S6-TDK  [C0603]  274.32 205.99 180 bottom
C347  0.22U-25-X8R-S6-TDK  [C0603]  270.92 204.22 180 bottom
C348  0.22U-25-X8R-S6-TDK  [C0603]  274.32 214.88 180 bottom
C349  0.22U-25-X8R-S6-TDK  [C0603]  274.32 222 180 bottom
C350  0.22U-25-X8R-S6-TDK  [C0603]  274.32 209.55 180 bottom
C351  0.22U-25-X8R-S6-TDK  [C0603]  274.32 218.44 180 bottom
C352  0.22U-25-X8R-S6-TDK  [C0603]  274.32 223.77 180 bottom
C353  0.22U-25-X8R-S6-TDK  [C0603]  274.32 220.22 180 bottom
C354  0.22U-25-X8R-S6-TDK  [C0603]  274.32 225.55 180 bottom
C355  0.22U-25-X8R-S6-TDK  [C0603]  274.32 216.66 180 bottom
C356  0.22U-25-X8R-S6-TDK  [C0603]  274.32 204.22 180 bottom
C357  0.22U-25-X8R-S6-TDK  [C0603]  274.32 207.77 180 bottom
C358  0.22U-25-X8R-S6-TDK  [C0603]  274.32 211.33 180 bottom
C359  0.22U-25-X8R-S6-TDK  [C0603]  274.32 202.44 180 bottom
C360  0.22U-25-X8R-S6-TDK  [C0603]  270.92 205.99 180 bottom
C361  0.22U-25-X8R-S6-TDK  [C0603]  274.32 213.11 180 bottom
C362  NC/10U-25-X-S6-MU  [C0603]  265.94 224.03 180 bottom
C363  NC/470U-4-T-SD-LOESR  [CODE_D]  245.11 208.03 180 bottom
C364  NC/22U-25-X-S8-MU  [C0805]  259.08 214.88 0 bottom
C365  NC/22U-25-X-S8-MU  [C0805]  259.08 218.44 0 bottom
C366  NC/22U-25-X-S8-MU  [C0805]  259.08 222 180 bottom
C367  NC/470U-4-T-SD-LOESR  [CODE_D]  245.11 201.93 180 bottom
C368  NC/470U-4-T-SD-LOESR  [CODE_D]  245.11 213.61 180 bottom
C369  NC/1U-25-X7R-S6-YA  [C0603]  270.51 223.77 180 bottom
C370  NC/0.1U-25-X7R-S4-MU  [C0402]  270.76 225.55 180 bottom
C371  NC/4.7U-25-X7R-S8-TY  [C0805]  270.51 222 180 bottom
C372  NC/10U-25-X7R-SA  [C1206]  265.18 222 180 bottom
C373  NC/22U-25-X7R-SB-MU  [C1210]  247.14 236.47 180 bottom
C374  NC/1U-25-X7R-S6-YA  [C0603]  310.74 207.26 0 bottom
C375  NC/0.1U-25-X7R-S4-MU  [C0402]  307.34 226.82 0 bottom
C376  NC/10U-25-X7R-SA  [C1206]  319.41 208.53 0 bottom
C377  NC/4.7U-25-X7R-S8-TY  [C0805]  310.84 205.49 0 bottom
C378  NC/22U-25-X7R-SB-MU  [C1210]  329.82 204.98 0 bottom
C379  NC/10U-25-X-S6-MU  [C0603]  310.74 203.71 0 bottom
C380  NC/470U-4-T-SD-LOESR  [CODE_D]  340.23 210.82 0 bottom
C381  NC/22U-25-X-S8-MU  [C0805]  319.01 204.98 0 bottom
C382  NC/22U-25-X-S8-MU  [C0805]  324.11 208.53 0 bottom
C383  NC/22U-25-X-S8-MU  [C0805]  324.11 204.98 0 bottom
C384  NC/470U-4-T-SD-LOESR  [CODE_D]  340.23 204.98 0 bottom
C385  NC/470U-4-T-SD-LOESR  [CODE_D]  340.23 198.37 0 bottom
C386  0.47U-25-X5R-S6-SS  [C0603]  310.74 209.04 0 bottom
C387  0.47U-25-X5R-S6-SS  [C0603]  310.74 221.49 0 bottom
C388  0.47U-25-X5R-S6-SS  [C0603]  310.74 219.71 0 bottom
C389  0.47U-25-X5R-S6-SS  [C0603]  310.74 217.93 0 bottom
C390  0.47U-25-X5R-S6-SS  [C0603]  310.74 216.15 0 bottom
C391  0.47U-25-X5R-S6-SS  [C0603]  310.74 214.38 0 bottom
C392  0.47U-25-X5R-S6-SS  [C0603]  310.74 212.6 0 bottom
C393  0.47U-25-X5R-S6-SS  [C0603]  310.74 210.82 0 bottom
C394  10U-25-X-S6-MU  [C0603]  314.13 225.04 0 bottom
C395  470U-4-T-SD-LOESR  [CODE_D]  354.2 204.85 0 bottom
C396  10U-25-X-S6-MU  [C0603]  314.24 223.27 0 bottom
C397  10U-25-X-S6-MU  [C0603]  314.2 226.82 0 bottom
C398  470U-4-T-SD-LOESR  [CODE_D]  354.2 198.75 0 bottom
C399  470U-4-T-SD-LOESR  [CODE_D]  354.11 210.82 0 bottom
C400  0.22U-25-X8R-S6-TDK  [C0603]  307.34 216.15 0 bottom
C401  0.22U-25-X8R-S6-TDK  [C0603]  307.34 214.38 0 bottom
C402  0.22U-25-X8R-S6-TDK  [C0603]  307.34 212.6 0 bottom
C403  0.22U-25-X8R-S6-TDK  [C0603]  310.74 225.04 0 bottom
C404  0.22U-25-X8R-S6-TDK  [C0603]  310.74 223.27 0 bottom
C405  0.22U-25-X8R-S6-TDK  [C0603]  307.34 203.71 0 bottom
C406  0.22U-25-X8R-S6-TDK  [C0603]  307.34 205.49 0 bottom
C407  0.22U-25-X8R-S6-TDK  [C0603]  307.34 210.82 0 bottom
C408  0.22U-25-X8R-S6-TDK  [C0603]  307.34 217.93 0 bottom
C409  0.22U-25-X8R-S6-TDK  [C0603]  307.34 207.26 0 bottom
C410  0.22U-25-X8R-S6-TDK  [C0603]  307.34 209.04 0 bottom
C411  0.22U-25-X8R-S6-TDK  [C0603]  310.74 226.82 0 bottom
C412  0.22U-25-X8R-S6-TDK  [C0603]  307.34 225.04 0 bottom
C413  0.22U-25-X8R-S6-TDK  [C0603]  307.34 223.27 0 bottom
C414  0.22U-25-X8R-S6-TDK  [C0603]  307.34 221.49 0 bottom
C415  0.22U-25-X8R-S6-TDK  [C0603]  307.34 219.71 0 bottom
C416  0.01U-25-X-S2-MU  [C0201]  337.44 230.89 180 bottom
C417  0.01U-25-X-S2-MU  [C0201]  337.44 248.16 180 bottom
C418  0.01U-25-X-S2-MU  [C0201]  292.65 183.61 180 bottom
C419  NC/1U-25-X7R-S6-YA  [C0603]  279.91 194.82 270 bottom
C420  NC/0.1U-25-X7R-S4-MU  [C0402]  281.69 195.07 270 bottom
C421  NC/10U-25-X7R-SA  [C1206]  279.91 185.42 270 bottom
C422  NC/4.7U-25-X7R-S8-TY  [C0805]  279.91 190.75 270 bottom
C423  NC/22U-25-X7R-SB-MU  [C1210]  265.68 175.51 270 bottom
C424  NC/10U-25-X-S6-MU  [C0603]  279.91 176.28 270 bottom
C425  NC/470U-4-T-SD-LOESR  [CODE_D]  245.18 166.24 180 bottom
C426  NC/22U-25-X-S8-MU  [C0805]  276.86 176.02 270 bottom
C427  NC/22U-25-X-S8-MU  [C0805]  269.75 176.02 270 bottom
C428  NC/22U-25-X-S8-MU  [C0805]  273.3 176.02 270 bottom
C429  NC/470U-4-T-SD-LOESR  [CODE_D]  245.18 172.08 180 bottom
C430  NC/470U-4-T-SD-LOESR  [CODE_D]  245.18 177.93 180 bottom
C431  0.47U-25-X5R-S6-SS  [C0603]  292.35 194.72 270 bottom
C432  0.47U-25-X5R-S6-SS  [C0603]  290.58 194.72 270 bottom
C433  0.47U-25-X5R-S6-SS  [C0603]  287.02 194.72 270 bottom
C434  0.47U-25-X5R-S6-SS  [C0603]  295.91 194.72 270 bottom
C435  0.47U-25-X5R-S6-SS  [C0603]  297.69 194.72 270 bottom
C436  0.47U-25-X5R-S6-SS  [C0603]  285.24 194.72 270 bottom
C437  0.47U-25-X5R-S6-SS  [C0603]  294.13 194.72 270 bottom
C438  10U-25-X-S6-MU  [C0603]  273.05 180.59 270 bottom
C439  0.47U-25-X5R-S6-SS  [C0603]  288.8 194.72 270 bottom
C440  470U-4-T-SD-LOESR  [CODE_D]  245.18 195.45 180 bottom
C441  10U-25-X-S6-MU  [C0603]  279.91 180.59 270 bottom
C442  10U-25-X-S6-MU  [C0603]  276.86 180.59 270 bottom
C443  470U-4-T-SD-LOESR  [CODE_D]  245.18 189.61 180 bottom
C444  470U-4-T-SD-LOESR  [CODE_D]  245.18 183.77 180 bottom
C445  0.22U-25-X8R-S6-TDK  [C0603]  287.02 198.12 270 bottom
C446  0.22U-25-X8R-S6-TDK  [C0603]  285.24 198.12 270 bottom
C447  0.22U-25-X8R-S6-TDK  [C0603]  301.24 198.12 270 bottom
C448  0.22U-25-X8R-S6-TDK  [C0603]  281.69 198.12 270 bottom
C449  0.22U-25-X8R-S6-TDK  [C0603]  283.46 198.12 270 bottom
C450  0.22U-25-X8R-S6-TDK  [C0603]  279.91 198.12 270 bottom
C451  0.22U-25-X8R-S6-TDK  [C0603]  294.13 198.12 270 bottom
C452  0.22U-25-X8R-S6-TDK  [C0603]  299.47 198.12 270 bottom
C453  0.22U-25-X8R-S6-TDK  [C0603]  290.58 198.12 270 bottom
C454  0.22U-25-X8R-S6-TDK  [C0603]  283.46 194.82 270 bottom
C455  0.22U-25-X8R-S6-TDK  [C0603]  292.35 198.12 270 bottom
C456  0.22U-25-X8R-S6-TDK  [C0603]  295.91 198.12 270 bottom
C457  0.22U-25-X8R-S6-TDK  [C0603]  297.69 198.12 270 bottom
C458  0.22U-25-X8R-S6-TDK  [C0603]  288.8 198.12 270 bottom
C459  0.22U-25-X8R-S6-TDK  [C0603]  301.24 194.72 270 bottom
C460  0.22U-25-X8R-S6-TDK  [C0603]  299.47 194.72 270 bottom
C461  0.1U-10-X-S2-MU  [C0201]  348.67 235.28 0 bottom
C462  0.1U-10-X-S2-MU  [C0201]  344.36 238.33 180 bottom
C463  0.1U-10-X-S2-MU  [C0201]  347.15 234.52 270 bottom
C464  0.1U-10-X-S2-MU  [C0201]  348.17 241.37 90 bottom
C465  0.1U-10-X-S2-MU  [C0201]  347.15 241.37 90 bottom
C466  0.1U-10-X-S2-MU  [C0201]  350.45 237.06 270 bottom
C467  0.1U-25-X7R-S4-MU  [C0402]  355.53 242.9 0 bottom
C468  0.01U-25-X-S2-MU  [C0201]  355.28 241.88 0 bottom
C469  10U-10-X-S6-MU  [C0603]  352.99 235.53 180 bottom
C470  0.1U-25-X7R-S4-MU  [C0402]  54.99 220.9 180 bottom
C471  0.1U-25-X7R-S4-MU  [C0402]  54.99 203.75 180 bottom
C472  0.01U-25-X-S2-MU  [C0201]  55.09 219.88 180 bottom
C473  0.01U-25-X-S2-MU  [C0201]  55.09 202.74 180 bottom
C474  0.1U-25-X7R-S4-MU  [C0402]  54.99 162.94 180 bottom
C475  0.01U-25-X-S2-MU  [C0201]  55.09 161.93 180 bottom
C476  0.1U-25-X7R-S4-MU  [C0402]  54.99 180.09 180 bottom
C477  0.01U-25-X-S2-MU  [C0201]  55.09 179.07 180 bottom
CB1  0.1U-25-X-S6  [C0603]  171.02 137.92 180 bottom
CB2  10U-25-X7R-SA  [C1206]  171.7 135.64 180 bottom
CB3  0.1U-25-X-S6  [C0603]  321.06 132.84 180 bottom
CB4  10U-25-X7R-SA  [C1206]  321.74 130.55 180 bottom
CB5  0.1U-25-X-S6  [C0603]  422.27 284.48 270 bottom
CB6  10U-25-X7R-SA  [C1206]  425.45 284.48 270 bottom
CB7  0.1U-25-X-S6  [C0603]  207.52 297.56 180 bottom
CB8  10U-25-X7R-SA  [C1206]  208.21 295.27 180 bottom
CB9  0.1U-25-X-S6  [C0603]  33.65 132.08 180 bottom
CB10  10U-25-X7R-SA  [C1206]  33.65 129.54 180 bottom
CB15  0.1U-25-X-S6  [C0603]  97.66 300.61 180 bottom
CB16  10U-25-X7R-SA  [C1206]  98.35 298.32 180 bottom
CSDPS225  V93K_CSDPS_DPS32  [PG_VG93K_PF_DPS32_G8D225]  254 331.47 0 top
CSDPS226  V93K_CSDPS  [PG_VG93K_PF_DPS32_G8D226]  254 351.79 0 top
CSDPS229  V93K_CSDPS_DPS32  [PG_VG93K_PF_DPS32_G8D229]  180.34 331.47 0 top
CSDPS425  V93K_CSDPS_DPS32  [PG_VG93K_PF_DPS32_G8D425]  254 341.63 0 top
CSDPS426  V93K_CSDPS  [PG_VG93K_PF_DPS32_G8D426]  254 361.95 0 top
CSDPS429  V93K_CSDPS_DPS32  [PG_VG93K_PF_DPS32_G8D429]  180.34 341.63 0 top
D101  V93K_CH  [PG_VG93K_F_G1D101]  327.66 97.79 0 top
D102  V93K_CH  [PG_VG93K_F_G1D102]  327.66 77.47 0 top
D103  V93K_CH  [PG_VG93K_F_G1D103]  327.66 57.15 0 top
D104  V93K_CH  [PG_VG93K_F_G1D104]  327.66 36.83 0 top
D105  V93K_CH  [PG_VG93K_F_G1D105]  401.32 97.79 0 top
D106  V93K_CH  [PG_VG93K_F_G1D106]  401.32 77.47 0 top
D107  V93K_CH  [PG_VG93K_F_G1D107]  401.32 57.15 0 top
D108  V93K_CH  [PG_VG93K_F_G1D108]  401.32 36.83 0 top
D109  V93K_CH  [PG_VG93K_F_G2D109]  401.32 331.47 0 top
D110  V93K_CH  [PG_VG93K_F_G2D110]  401.32 351.79 0 top
D111  V93K_CH  [PG_VG93K_F_G2D111]  401.32 372.11 0 top
D112  V93K_CH  [PG_VG93K_F_G2D112]  401.32 392.43 0 top
D113  V93K_CH  [PG_VG93K_F_G2D113]  327.66 331.47 0 top
D114  V93K_CH  [PG_VG93K_F_G2D114]  327.66 351.79 0 top
D115  V93K_CH  [PG_VG93K_F_G2D115]  327.66 372.11 0 top
D116  V93K_CH  [PG_VG93K_F_G2D116]  327.66 392.43 0 top
D117  V93K_CH  [PG_VG93K_F_G3D117]  180.34 97.79 0 top
D118  V93K_CH  [PG_VG93K_F_G3D118]  180.34 77.47 0 top
D119  V93K_CH  [PG_VG93K_F_G3D119]  180.34 57.15 0 top
D120  V93K_CH  [PG_VG93K_F_G3D120]  180.34 36.83 0 top
D121  V93K_CH  [PG_VG93K_F_G3D121]  254 97.79 0 top
D122  V93K_CH  [PG_VG93K_F_G3D122]  254 77.47 0 top
D123  V93K_CH  [PG_VG93K_F_G3D123]  254 57.15 0 top
D124  V93K_CH  [PG_VG93K_F_G3D124]  254 36.83 0 top
D125  V93K_CH  [PG_VG93K_F_G4D125]  33.02 97.79 0 top
D126  V93K_CH  [PG_VG93K_F_G4D126]  33.02 77.47 0 top
D127  V93K_CH  [PG_VG93K_F_G4D127]  33.02 57.15 0 top
D128  V93K_CH  [PG_VG93K_F_G4D128]  33.02 36.83 0 top
D129  V93K_CH  [PG_VG93K_F_G4D129]  106.68 97.79 0 top
D130  V93K_CH  [PG_VG93K_F_G4D130]  106.68 77.47 0 top
D131  V93K_CH  [PG_VG93K_F_G4D131]  106.68 57.15 0 top
D132  V93K_CH  [PG_VG93K_F_G4D132]  106.68 36.83 0 top
D217  V93K_CH  [PG_VG93K_F_G7D217]  106.68 331.47 0 top
D218  V93K_CH  [PG_VG93K_F_G7D218]  106.68 351.79 0 top
D219  V93K_CH  [PG_VG93K_F_G7D219]  106.68 372.11 0 top
D220  V93K_CH  [PG_VG93K_F_G7D220]  106.68 392.43 0 top
D221  V93K_CH  [PG_VG93K_F_G7D221]  33.02 331.47 0 top
D222  V93K_CH  [PG_VG93K_F_G7D222]  33.02 351.79 0 top
D223  V93K_CH  [PG_VG93K_F_G7D223]  33.02 372.11 0 top
D224  V93K_CH  [PG_VG93K_F_G7D224]  33.02 392.43 0 top
D227  V93K_CH  [PG_VG93K_F_G8D227]  254 372.11 0 top
D228  V93K_CH  [PG_VG93K_F_G8D228]  254 392.43 0 top
D231  V93K_CH  [PG_VG93K_F_G8D231]  180.34 372.11 0 top
D232  V93K_CH  [PG_VG93K_F_G8D232]  180.34 392.43 0 top
D301  V93K_CH  [PG_VG93K_F_G1D301]  327.66 87.63 0 top
D302  V93K_CH  [PG_VG93K_F_G1D302]  327.66 67.31 0 top
D303  V93K_CH  [PG_VG93K_F_G1D303]  327.66 46.99 0 top
D304  V93K_CH  [PG_VG93K_F_G1D304]  327.66 26.67 0 top
D305  V93K_CH  [PG_VG93K_F_G1D305]  401.32 87.63 0 top
D306  V93K_CH  [PG_VG93K_F_G1D306]  401.32 67.31 0 top
D307  V93K_CH  [PG_VG93K_F_G1D307]  401.32 46.99 0 top
D308  V93K_CH  [PG_VG93K_F_G1D308]  401.32 26.67 0 top
D309  V93K_CH  [PG_VG93K_F_G2D309]  401.32 341.63 0 top
D310  V93K_CH  [PG_VG93K_F_G2D310]  401.32 361.95 0 top
D311  V93K_CH  [PG_VG93K_F_G2D311]  401.32 382.27 0 top
D312  V93K_CH  [PG_VG93K_F_G2D312]  401.32 402.59 0 top
D313  V93K_CH  [PG_VG93K_F_G2D313]  327.66 341.63 0 top
D314  V93K_CH  [PG_VG93K_F_G2D314]  327.66 361.95 0 top
D315  V93K_CH  [PG_VG93K_F_G2D315]  327.66 382.27 0 top
D316  V93K_CH  [PG_VG93K_F_G2D316]  327.66 402.59 0 top
D317  V93K_CH  [PG_VG93K_F_G3D317]  180.34 87.63 0 top
D318  V93K_CH  [PG_VG93K_F_G3D318]  180.34 67.31 0 top
D319  V93K_CH  [PG_VG93K_F_G3D319]  180.34 46.99 0 top
D320  V93K_CH  [PG_VG93K_F_G3D320]  180.34 26.67 0 top
D321  V93K_CH  [PG_VG93K_F_G3D321]  254 87.63 0 top
D322  V93K_CH  [PG_VG93K_F_G3D322]  254 67.31 0 top
D323  V93K_CH  [PG_VG93K_F_G3D323]  254 46.99 0 top
D427  V93K_CH  [PG_VG93K_F_G8D427]  254 382.27 0 top
D428  V93K_CH  [PG_VG93K_F_G8D428]  254 402.59 0 top
D431  V93K_CH  [PG_VG93K_F_G8D431]  180.34 382.27 0 top
D432  V93K_CH  [PG_VG93K_F_G8D432]  180.34 402.59 0 top
DPS1  V93K_DPS  [PG_VG93K_F_G1DPS1]  401.32 16.51 0 top
DPS2  V93K_DPS  [PG_VG93K_F_G2DPS2]  327.66 412.75 0 top
DPS3  V93K_DPS  [PG_VG93K_F_G3DPS3]  254 16.51 0 top
DPS4  V93K_DPS  [PG_VG93K_F_G4DPS4]  106.68 16.51 0 top
DPS7  V93K_DPS  [PG_VG93K_F_G7DPS7]  33.02 412.75 0 top
DPS8  V93K_DPS  [PG_VG93K_F_G8DPS8]  180.34 412.75 0 top
DUT_GND  TP01  [TP_040_T]  319.44 452.5 0 top
DUT_GND1  TP01  [TP_040_T]  321.73 452.5 0 top
DUT_GND2  TP01  [TP_040_T]  324.02 452.5 0 top
DUT_GND3  TP01  [TP_040_T]  326.3 452.5 0 top
DUT_GND4  TP01  [TP_040_T]  328.59 452.5 0 top
DUT_GND5  TP01  [TP_040_T]  330.87 452.5 0 top
DV2  LDG-2-S6  [LED_0603]  321.94 227.08 90 top
DV3  LDG-2-S6  [LED_0603]  321.94 244.35 90 top
DV4  LDG-2-S6  [LED_0603]  293.1 251.77 0 top
DV5  LDG-2-S6  [LED_0603]  282.05 251.77 0 top
DV6  LDG-2-S6  [LED_0603]  253.69 205.73 90 top
DV7  LDG-2-S6  [LED_0603]  330.89 216.93 270 top
DV8  LDG-2-S6  [LED_0603]  298.97 177.75 180 top
DV9  LDG-2-S6  [LED_0603]  330.89 199.66 270 top
DV10  LDG-2-S6  [LED_0603]  286.78 177.75 180 top
DV11  LDG-2-S6  [LED_0603]  355.02 229.88 270 top
DV12  LDG-2-S6  [LED_0603]  355.02 247.15 270 top
DV13  LDG-2-S6  [LED_0603]  372.29 241.57 270 top
DV14  LDG-2-S6  [LED_0603]  73.08 218.07 270 top
DV15  LDG-2-S6  [LED_0603]  73.08 200.92 270 top
DV16  LDG-2-S6  [LED_0603]  39.75 215.73 90 top
DV17  LDG-2-S6  [LED_0603]  39.75 198.58 90 top
DV18  LDG-2-S6  [LED_0603]  73.08 160.11 270 top
DV19  LDG-2-S6  [LED_0603]  39.75 157.77 90 top
DV20  LDG-2-S6  [LED_0603]  73.08 177.25 270 top
DV21  LDG-2-S6  [LED_0603]  39.75 174.92 90 top
FD1  -  [FD_040_V2]  21.59 135.89 0 top
FD2  -  [FD_040_V2]  161.29 133.35 0 top
FD3  -  [FD_040_V2]  420.37 133.35 0 top
FD4  -  [FD_040_V2]  291.46 132.71 0 top
FD5  -  [FD_040_V2]  291.46 297.81 0 top
FD6  -  [FD_040_V2]  420.37 293.37 0 top
FD7  -  [FD_040_V2]  161.29 293.37 0 top
FD8  -  [FD_040_V2]  16.51 295.91 0 top
FD9  -  [FD_040_V2]  21.59 135.89 180 bottom
FD10  -  [FD_040_V2]  161.29 133.35 180 bottom
FD11  -  [FD_040_V2]  420.37 133.35 180 bottom
FD12  -  [FD_040_V2]  291.46 132.71 180 bottom
FD13  -  [FD_040_V2]  291.46 297.81 180 bottom
FD14  -  [FD_040_V2]  420.37 293.37 180 bottom
FD15  -  [FD_040_V2]  161.29 293.37 180 bottom
FD16  -  [FD_040_V2]  16.51 295.91 180 bottom
FSH0AS148AA  REF-CODE-CHIP  [CHIP_CODE]  69.34 270.26 0 top
K1  SGRF303-5-A  [RL_SGRF303_5V]  328.29 228.6 90 bottom
K2  SGRF303-5-A  [RL_SGRF303_5V]  328.29 245.87 90 bottom
K3  UA2-5NJ-A-V3  [RL_NECUA2_5V_V3]  294.13 245.62 90 bottom
K4  UA2-5NJ-A-V3  [RL_NECUA2_5V_V3]  283.08 245.62 90 bottom
K5  UA2-5NJ-A-V3  [RL_NECUA2_5V_V3]  259.84 206.76 180 bottom
K6  UA2-5NJ-A-V3  [RL_NECUA2_5V_V3]  324.74 215.9 0 bottom
K7  UA2-5NJ-A-V3  [RL_NECUA2_5V_V3]  297.94 183.9 270 bottom
K8  UA2-5NJ-A-V3  [RL_NECUA2_5V_V3]  324.74 198.63 0 bottom
K9  UA2-5NJ-A-V3  [RL_NECUA2_5V_V3]  285.75 183.9 270 bottom
K10  UA2-5NJ-A-V3  [RL_NECUA2_5V_V3]  348.87 228.85 0 bottom
K11  UA2-5NJ-A-V3  [RL_NECUA2_5V_V3]  348.87 246.13 0 bottom
K12  UA2-5NJ-A-V3  [RL_NECUA2_5V_V3]  366.14 240.54 0 bottom
K13  UA2-5NJ-A-V3  [RL_NECUA2_5V_V3]  67.31 217.21 0 bottom
K14  UA2-5NJ-A-V3  [RL_NECUA2_5V_V3]  67.31 200.07 0 bottom
K15  SGRF303-5-A  [RL_SGRF303_5V]  46.35 216.71 90 bottom
K16  SGRF303-5-A  [RL_SGRF303_5V]  46.35 199.56 90 bottom
K17  UA2-5NJ-A-V3  [RL_NECUA2_5V_V3]  67.31 159.26 0 bottom
K18  SGRF303-5-A  [RL_SGRF303_5V]  46.35 158.75 90 bottom
K19  UA2-5NJ-A-V3  [RL_NECUA2_5V_V3]  67.31 176.4 0 bottom
K20  SGRF303-5-A  [RL_SGRF303_5V]  46.35 175.89 90 bottom
KS1  NC/712D-5-V2  [RL_712D_5V_V2]  163.19 164.47 180 bottom
KS1-2  TP03-D  [TP_060_040]  157.61 161.93 0 top
KS1-3  TP03-D  [TP_060_040]  157.35 166.24 0 top
KS1-4  TP03-D  [TP_060_040]  159.64 169.54 0 top
KS1-6  TP03-D  [TP_060_040]  166.75 169.54 0 top
KS1-7  TP03-D  [TP_060_040]  169.04 166.24 0 top
KS1-8  TP03-D  [TP_060_040]  168.78 161.93 0 top
KS2  NC/712D-5-V2  [RL_712D_5V_V2]  180.34 164.47 180 bottom
KS2-2  TP03-D  [TP_060_040]  174.75 161.93 0 top
KS2-3  TP03-D  [TP_060_040]  174.5 166.24 0 top
KS2-4  TP03-D  [TP_060_040]  176.78 169.54 0 top
KS2-6  TP03-D  [TP_060_040]  183.9 169.54 0 top
KS2-7  TP03-D  [TP_060_040]  186.18 166.24 0 top
KS2-8  TP03-D  [TP_060_040]  185.93 161.93 0 top
KS3  NC/2911-05-321-A-V2  [RL_COTO2911_5V_RLPIN]  177.8 187.96 180 bottom
KS3-4  TP03-D  [TP_060_040]  181.36 188.47 0 top
KS3-5  TP03-D  [TP_060_040]  181.36 184.91 0 top
KS3-8  TP03-D  [TP_060_040]  156.46 185.42 0 top
KS4  NC/2911-05-321-A-V2  [RL_COTO2911_5V_RLPIN]  177.8 179.07 180 bottom
KS4-4  TP03-D  [TP_060_040]  181.36 179.58 0 top
KS4-5  TP03-D  [TP_060_040]  181.36 176.02 0 top
KS4-8  TP03-D  [TP_060_040]  156.46 176.53 0 top
LDB1  LDG-2-S6  [LED_0603]  164.46 158.88 180 top
LDB2  LDG-2-S6  [LED_0603]  181.61 158.88 180 top
LDB3  LDG-2-S6  [LED_0603]  167.39 190.5 0 top
LDB4  LDG-2-S6  [LED_0603]  167.39 181.61 0 top
LDB5  LDG-2-S8  [LED_0805]  97.03 293.88 0 top
LOGO1  -  [LOGO_KT_KSMT]  57.15 277.62 0 top
LOGO2  LOGO_FY_Faraday  [LOGO_FY_FARADAY]  64.26 240.79 0 top
LRB1  470-1-S4  [R0402]  161.67 158.88 0 top
LRB2  470-1-S4  [R0402]  178.82 158.88 0 top
LRB3  470-1-S4  [R0402]  170.18 190.5 180 top
LRB4  470-1-S4  [R0402]  170.18 181.61 180 top
LRB5  330-1-S6  [R0603]  98.81 293.88 0 bottom
M1  V93K-TOUCHSENSOR-FY  [V93K_TOUCHSENSOR_FY]  290.83 214.63 0 top
NOREF  -  []  287.23 211.13 90 top
NOREF#2  -  []  325.07 230.94 0 top
NOREF#3  -  []  74.31 185.17 90 top
NOREF#4  -  []  254.59 203.76 90 top
NOREF#5  -  []  289.63 213.53 90 top
NOREF#6  -  []  265.83 239.63 90 top
NOREF#7  -  []  313.99 276.59 90 top
NOREF#8  -  []  344.49 276.01 90 top
NOREF#9  -  []  395.73 251.21 90 top
NOREF#10  -  []  327.57 276.31 90 top
NOREF#11  -  []  295.23 207.93 90 top
NOREF#12  -  []  284.58 213.31 0 top
NOREF#13  -  []  321.29 228.48 0 top
NOREF#14  -  []  271.36 223.32 90 top
NOREF#15  -  []  291.78 207.71 90 top
NOREF#16  -  []  47.59 195.77 90 top
NOREF#17  -  []  284.58 221.31 90 top
NOREF#18  -  []  344.06 238.33 0 top
NOREF#19  -  []  314.78 277.4 90 top
NOREF#20  -  []  294.39 172.72 90 top
NOREF#21  -  []  56.28 159.24 90 top
NOREF#22  -  []  349.27 230.45 0 top
NOREF#23  -  []  237.93 278.6 0 top
NOREF#24  -  []  321.94 243.6 90 top
NOREF#25  -  []  49.58 173.55 90 top
NOREF#26  -  []  271.77 210.88 90 top
NOREF#27  -  []  306.49 222.82 90 top
NOREF#28  -  []  328.93 277.7 90 top
NOREF#29  -  []  290.98 210.11 90 top
NOREF#30  -  []  285.93 177.3 90 top
NOREF#31  -  []  284.58 214.91 90 top
NOREF#32  -  []  290.18 217.31 90 top
NOREF#33  -  []  259.08 194.56 90 top
NOREF#34  -  []  272.54 183.64 90 top
NOREF#35  -  []  314.01 276.01 90 top
NOREF#36  -  []  288.58 218.91 0 top
NOREF#37  -  []  309.89 221.04 90 top
NOREF#38  -  []  295.78 208.51 90 top
NOREF#39  -  []  301.24 178.05 0 top
NOREF#40  -  []  346.21 238.62 0 top
NOREF#41  -  []  296.58 218.91 0 top
NOREF#42  -  []  284.58 219.71 0 top
NOREF#43  -  []  293.63 219.13 90 top
NOREF#44  -  []  275.17 207.32 90 top
NOREF#45  -  []  286.18 210.11 90 top
NOREF#46  -  []  237.49 276.31 90 top
NOREF#47  -  []  39.3 156.92 90 top
NOREF#48  -  []  65.51 201.67 0 top
NOREF#49  -  []  328.29 204.98 0 top
NOREF#50  -  []  286.43 219.93 90 top
NOREF#51  -  []  285.38 210.91 0 top
NOREF#52  -  []  54.49 162.25 0 top
NOREF#53  -  []  275.17 217.99 90 top
NOREF#54  -  []  292.03 219.13 90 top
NOREF#55  -  []  285.38 207.71 0 top
NOREF#56  -  []  314.13 276.01 90 top
NOREF#57  -  []  291.78 215.71 90 top
NOREF#58  -  []  296.58 217.31 90 top
NOREF#59  -  []  292.83 218.33 90 top
NOREF#60  -  []  328.34 214.3 0 top
NOREF#61  -  []  287.78 218.11 0 top
NOREF#62  -  []  282.89 277.4 0 top
NOREF#63  -  []  276.33 200.13 0 top
NOREF#64  -  []  287.78 206.91 90 top
NOREF#65  -  []  283.23 219.93 90 top
NOREF#66  -  []  355.47 229.03 90 top
NOREF#67  -  []  292.83 215.13 90 top
NOREF#68  -  []  284.03 214.33 90 top
NOREF#69  -  []  312 276.01 90 top
NOREF#70  -  []  72.69 174.01 90 top
NOREF#71  -  []  47.59 172.1 90 top
NOREF#72  -  []  298.45 277.7 90 top
NOREF#73  -  []  282.98 206.91 90 top
NOREF#74  -  []  287.78 214.91 90 top
NOREF#75  -  []  264.03 165.1 90 top
NOREF#76  -  []  253.17 276.01 0 top
NOREF#77  -  []  294.43 211.93 90 top
NOREF#78  -  []  56 177.66 0 top
NOREF#79  -  []  294.18 214.91 90 top
NOREF#80  -  []  298.43 222.33 90 top
NOREF#81  -  []  253.69 204.98 90 top
NOREF#82  -  []  297.38 219.71 0 top
NOREF#83  -  []  41.66 158.75 90 top
NOREF#84  -  []  56 160.51 0 top
NOREF#85  -  []  309.89 228.15 90 top
NOREF#86  -  []  72.56 197.07 90 top
NOREF#87  -  []  244.6 238.51 0 top
NOREF#88  -  []  237.49 277.7 90 top
NOREF#89  -  []  253.17 276.01 90 top
NOREF#90  -  []  298.12 177.3 0 top
NOREF#91  -  []  65.51 160.86 0 top
NOREF#92  -  []  283.23 207.13 90 top
NOREF#93  -  []  36.32 224.57 0 top
NOREF#94  -  []  292.58 216.51 0 top
NOREF#95  -  []  288.58 212.51 90 top
NOREF#96  -  []  297.38 214.91 90 top
NOREF#97  -  []  324.74 182.88 90 top
NOREF#98  -  []  279.08 247.22 0 top
NOREF#99  -  []  342.81 276.31 90 top
NOREF#100  -  []  293.38 218.91 90 top
NOREF#101  -  []  284.01 251.77 0 top
NOREF#102  -  []  302.83 195.67 0 top
NOREF#103  -  []  168.24 181.16 90 top
NOREF#104  -  []  265.83 183.43 90 top
NOREF#105  -  []  259.08 198.63 0 top
NOREF#106  -  []  282.61 277.7 0 top
NOREF#107  -  []  278.55 197.13 90 top
NOREF#108  -  []  354.83 239.85 90 top
NOREF#109  -  []  358.14 218.95 0 top
NOREF#110  -  []  286.98 218.91 90 top
NOREF#111  -  []  330.24 215.53 0 top
NOREF#112  -  []  295.23 209.53 90 top
NOREF#113  -  []  366.54 242.14 0 top
NOREF#114  -  []  275.17 221.55 90 top
NOREF#115  -  []  290.18 212.51 0 top
NOREF#116  -  []  289.38 208.51 90 top
NOREF#117  -  []  295.23 215.93 90 top
NOREF#118  -  []  72.56 156.26 90 top
NOREF#119  -  []  40.14 176.5 90 top
NOREF#120  -  []  73.08 217.32 90 top
NOREF#121  -  []  309.89 224.59 90 top
NOREF#122  -  []  294.69 251.38 0 top
NOREF#123  -  []  306.49 203.26 90 top
NOREF#124  -  []  284.03 209.53 90 top
NOREF#125  -  []  32.17 229.2 0 top
NOREF#126  -  []  285.63 209.53 90 top
NOREF#127  -  []  283.23 218.33 90 top
NOREF#128  -  []  297.38 216.51 90 top
NOREF#129  -  []  330.89 216.18 90 top
NOREF#130  -  []  235.8 276.01 0 top
NOREF#131  -  []  298.13 277.4 90 top
NOREF#132  -  []  337.48 230.13 0 top
NOREF#133  -  []  309.89 219.26 90 top
NOREF#134  -  []  327.57 277.7 90 top
NOREF#135  -  []  291.23 211.93 90 top
NOREF#136  -  []  321.91 132.39 90 top
NOREF#137  -  []  297.38 208.51 0 top
NOREF#138  -  []  273.33 197.13 0 top
NOREF#139  -  []  283.23 215.13 90 top
NOREF#140  -  []  323.6 228.6 90 top
NOREF#141  -  []  296.58 220.51 90 top
NOREF#142  -  []  336.84 230.57 90 top
NOREF#143  -  []  294.98 209.31 0 top
NOREF#144  -  []  294.18 213.31 90 top
NOREF#145  -  []  166.54 190.95 0 top
NOREF#146  -  []  284.58 221.31 0 top
NOREF#147  -  []  348.06 239.27 0 top
NOREF#148  -  []  63.31 201.67 0 top
NOREF#149  -  []  283.51 276.59 90 top
NOREF#150  -  []  285.38 177.1 90 top
NOREF#151  -  []  347.15 234.22 90 top
NOREF#152  -  []  314.13 278.6 0 top
NOREF#153  -  []  273.33 202.35 0 top
NOREF#154  -  []  344.87 230.45 0 top
NOREF#155  -  []  289.63 210.33 90 top
NOREF#156  -  []  297.63 221.53 90 top
NOREF#157  -  []  244.6 234.44 90 top
NOREF#158  -  []  329.25 276.01 90 top
NOREF#159  -  []  284.58 216.51 0 top
NOREF#160  -  []  322.94 200.23 0 top
NOREF#161  -  []  284.58 219.71 90 top
NOREF#162  -  []  286.18 214.91 0 top
NOREF#163  -  []  294.05 184.1 90 top
NOREF#164  -  []  292.58 216.51 90 top
NOREF#165  -  []  284.83 208.73 90 top
NOREF#166  -  []  39.36 201.75 0 top
NOREF#167  -  []  275.17 223.32 90 top
NOREF#168  -  []  297.55 277.38 0 top
NOREF#169  -  []  312 278.6 0 top
NOREF#170  -  []  294.18 208.51 90 top
NOREF#171  -  []  337.14 230.89 0 top
NOREF#172  -  []  296.58 212.51 90 top
NOREF#173  -  []  57.95 157.96 90 top
NOREF#174  -  []  95.93 294.6 0 top
NOREF#175  -  []  280.67 283.21 0 top
NOREF#176  -  []  342.48 278.6 0 top
NOREF#177  -  []  279.08 247.22 0 top
NOREF#178  -  []  294.98 218.91 90 top
NOREF#179  -  []  276.41 169.13 0 top
NOREF#180  -  []  285.38 207.71 90 top
NOREF#181  -  []  329.99 212.9 90 top
NOREF#182  -  []  39.75 214.98 90 top
NOREF#183  -  []  315.83 189.63 90 top
NOREF#184  -  []  287.78 218.11 90 top
NOREF#185  -  []  43.13 178.24 0 top
NOREF#186  -  []  290.25 189.3 0 top
NOREF#187  -  []  294.18 214.91 0 top
NOREF#188  -  []  298.18 206.11 90 top
NOREF#189  -  []  294.98 214.11 90 top
NOREF#190  -  []  283.23 221.53 90 top
NOREF#191  -  []  282.98 210.11 90 top
NOREF#192  -  []  257.81 233.17 0 top
NOREF#193  -  []  349.27 234.96 90 top
NOREF#194  -  []  287.78 213.31 0 top
NOREF#195  -  []  61.66 197.07 0 top
NOREF#196  -  []  286.18 218.11 90 top
NOREF#197  -  []  254.08 207.32 90 top
NOREF#198  -  []  291.23 216.73 90 top
NOREF#199  -  []  34.51 131.63 90 top
NOREF#200  -  []  283.78 212.51 90 top
NOREF#201  -  []  291.78 210.91 0 top
NOREF#202  -  []  240.03 283.21 90 top
NOREF#203  -  []  297.38 216.51 0 top
NOREF#204  -  []  286.18 214.91 90 top
NOREF#205  -  []  329.23 277.38 90 top
NOREF#206  -  []  290.89 180.94 0 top
NOREF#207  -  []  286.98 207.71 90 top
